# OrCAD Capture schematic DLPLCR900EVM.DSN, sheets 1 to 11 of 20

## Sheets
1 P20-Notes and Revisions
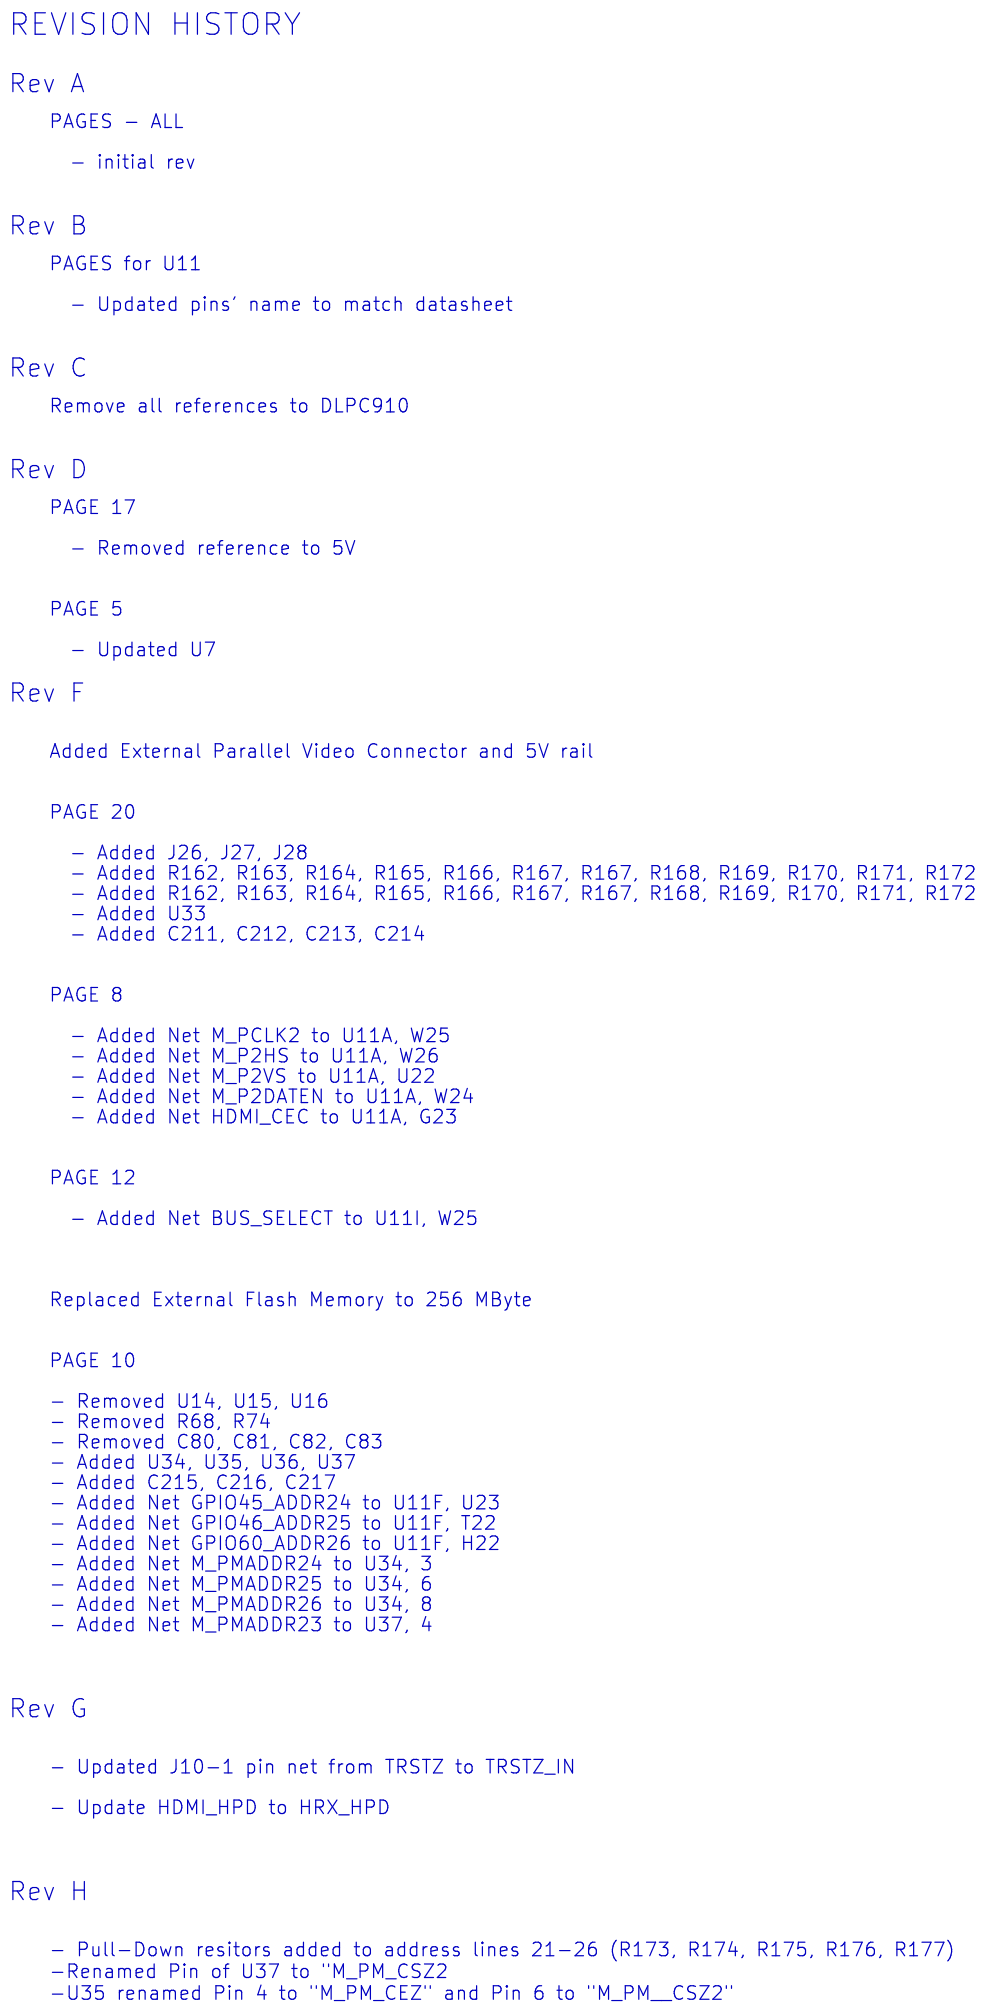
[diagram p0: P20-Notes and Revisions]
2 P19-External Parallel Source: size A3
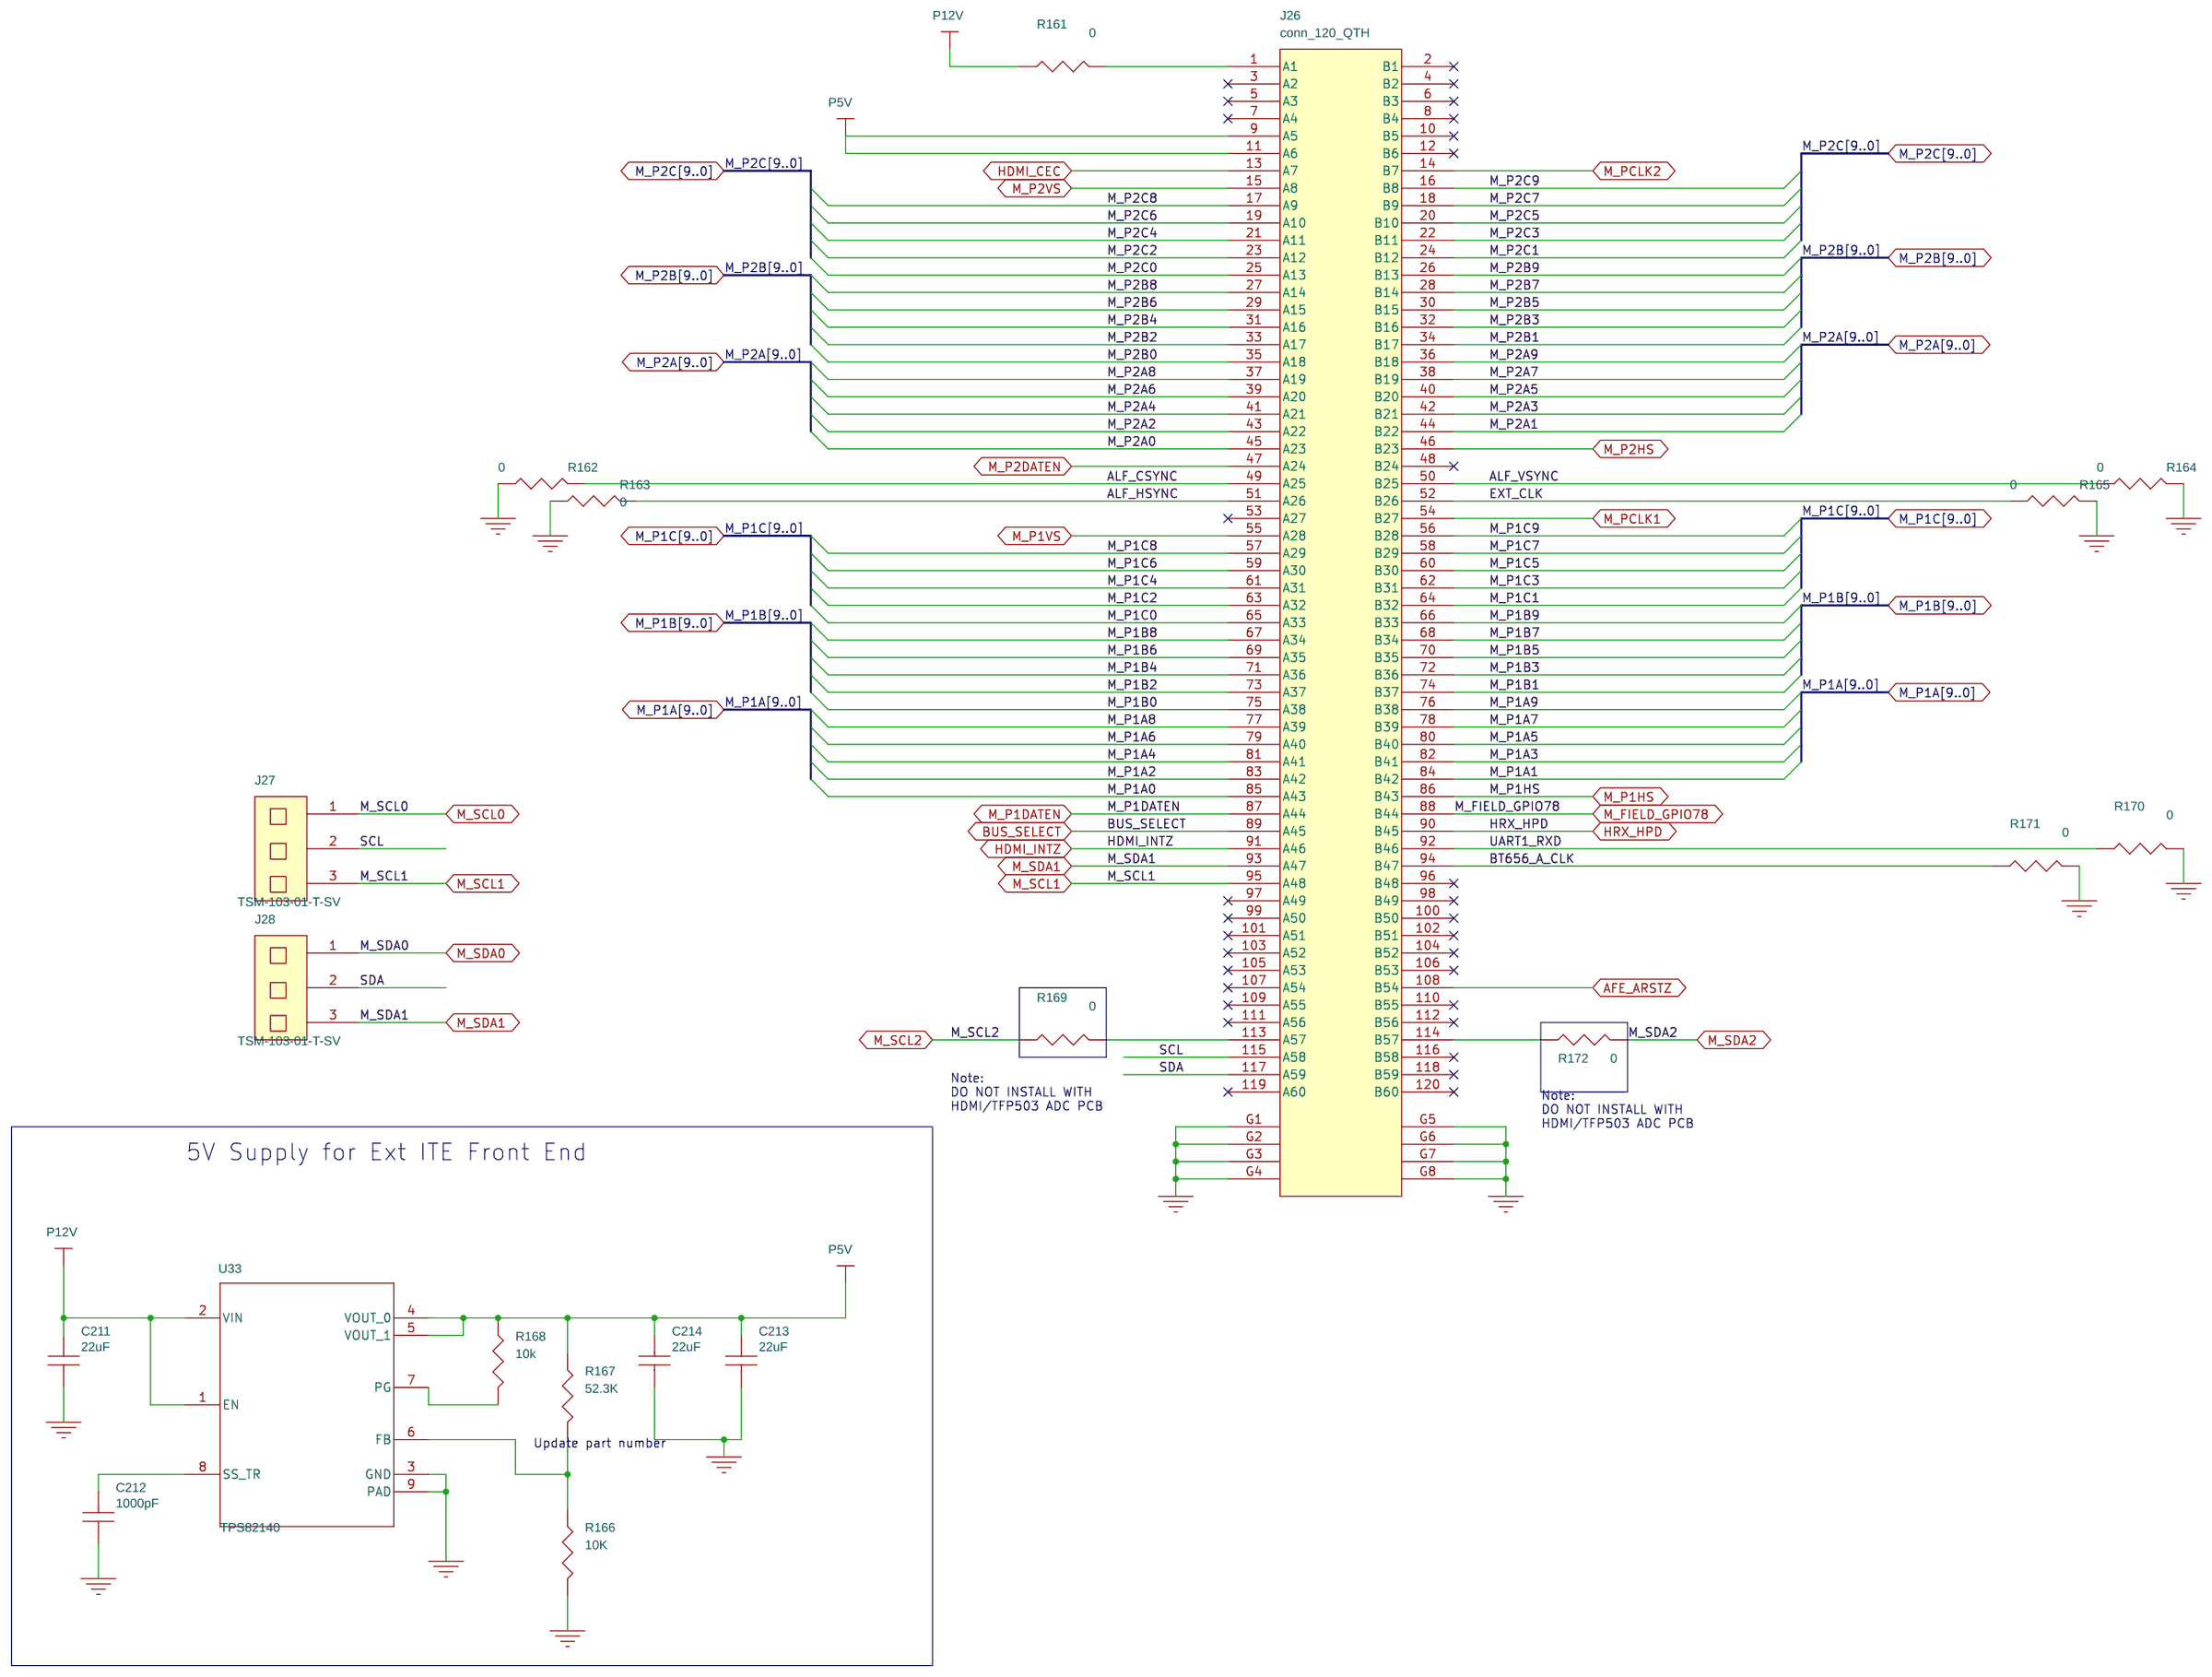
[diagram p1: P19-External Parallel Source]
3 P02-Import Notice
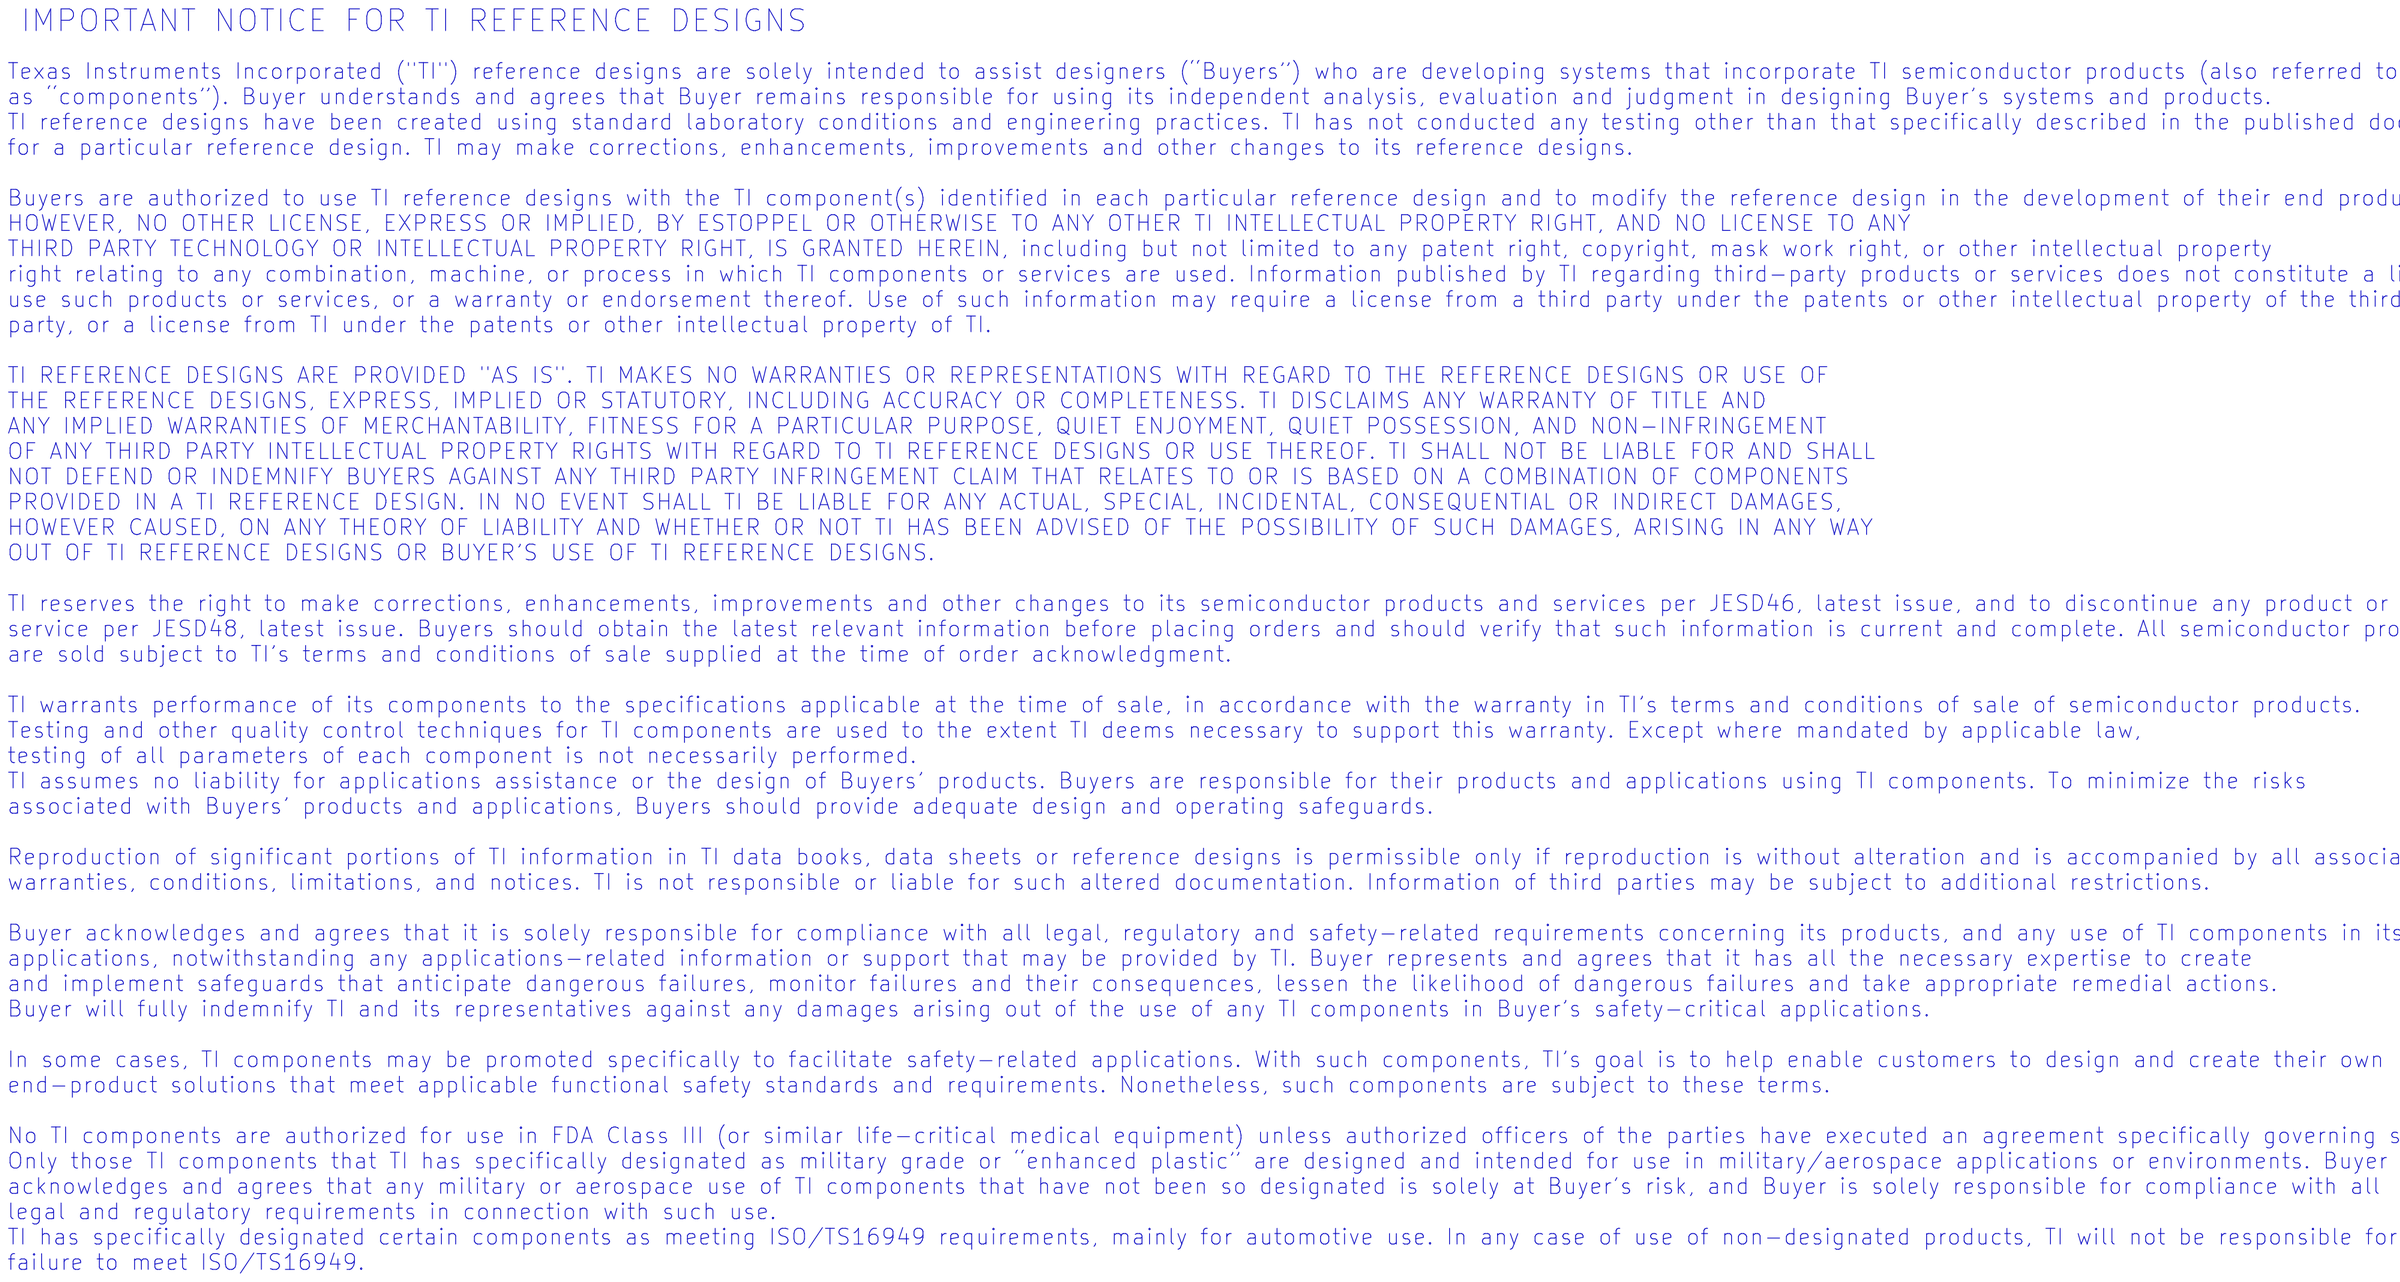
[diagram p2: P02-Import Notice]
4 P16-Power LDOs: size A3
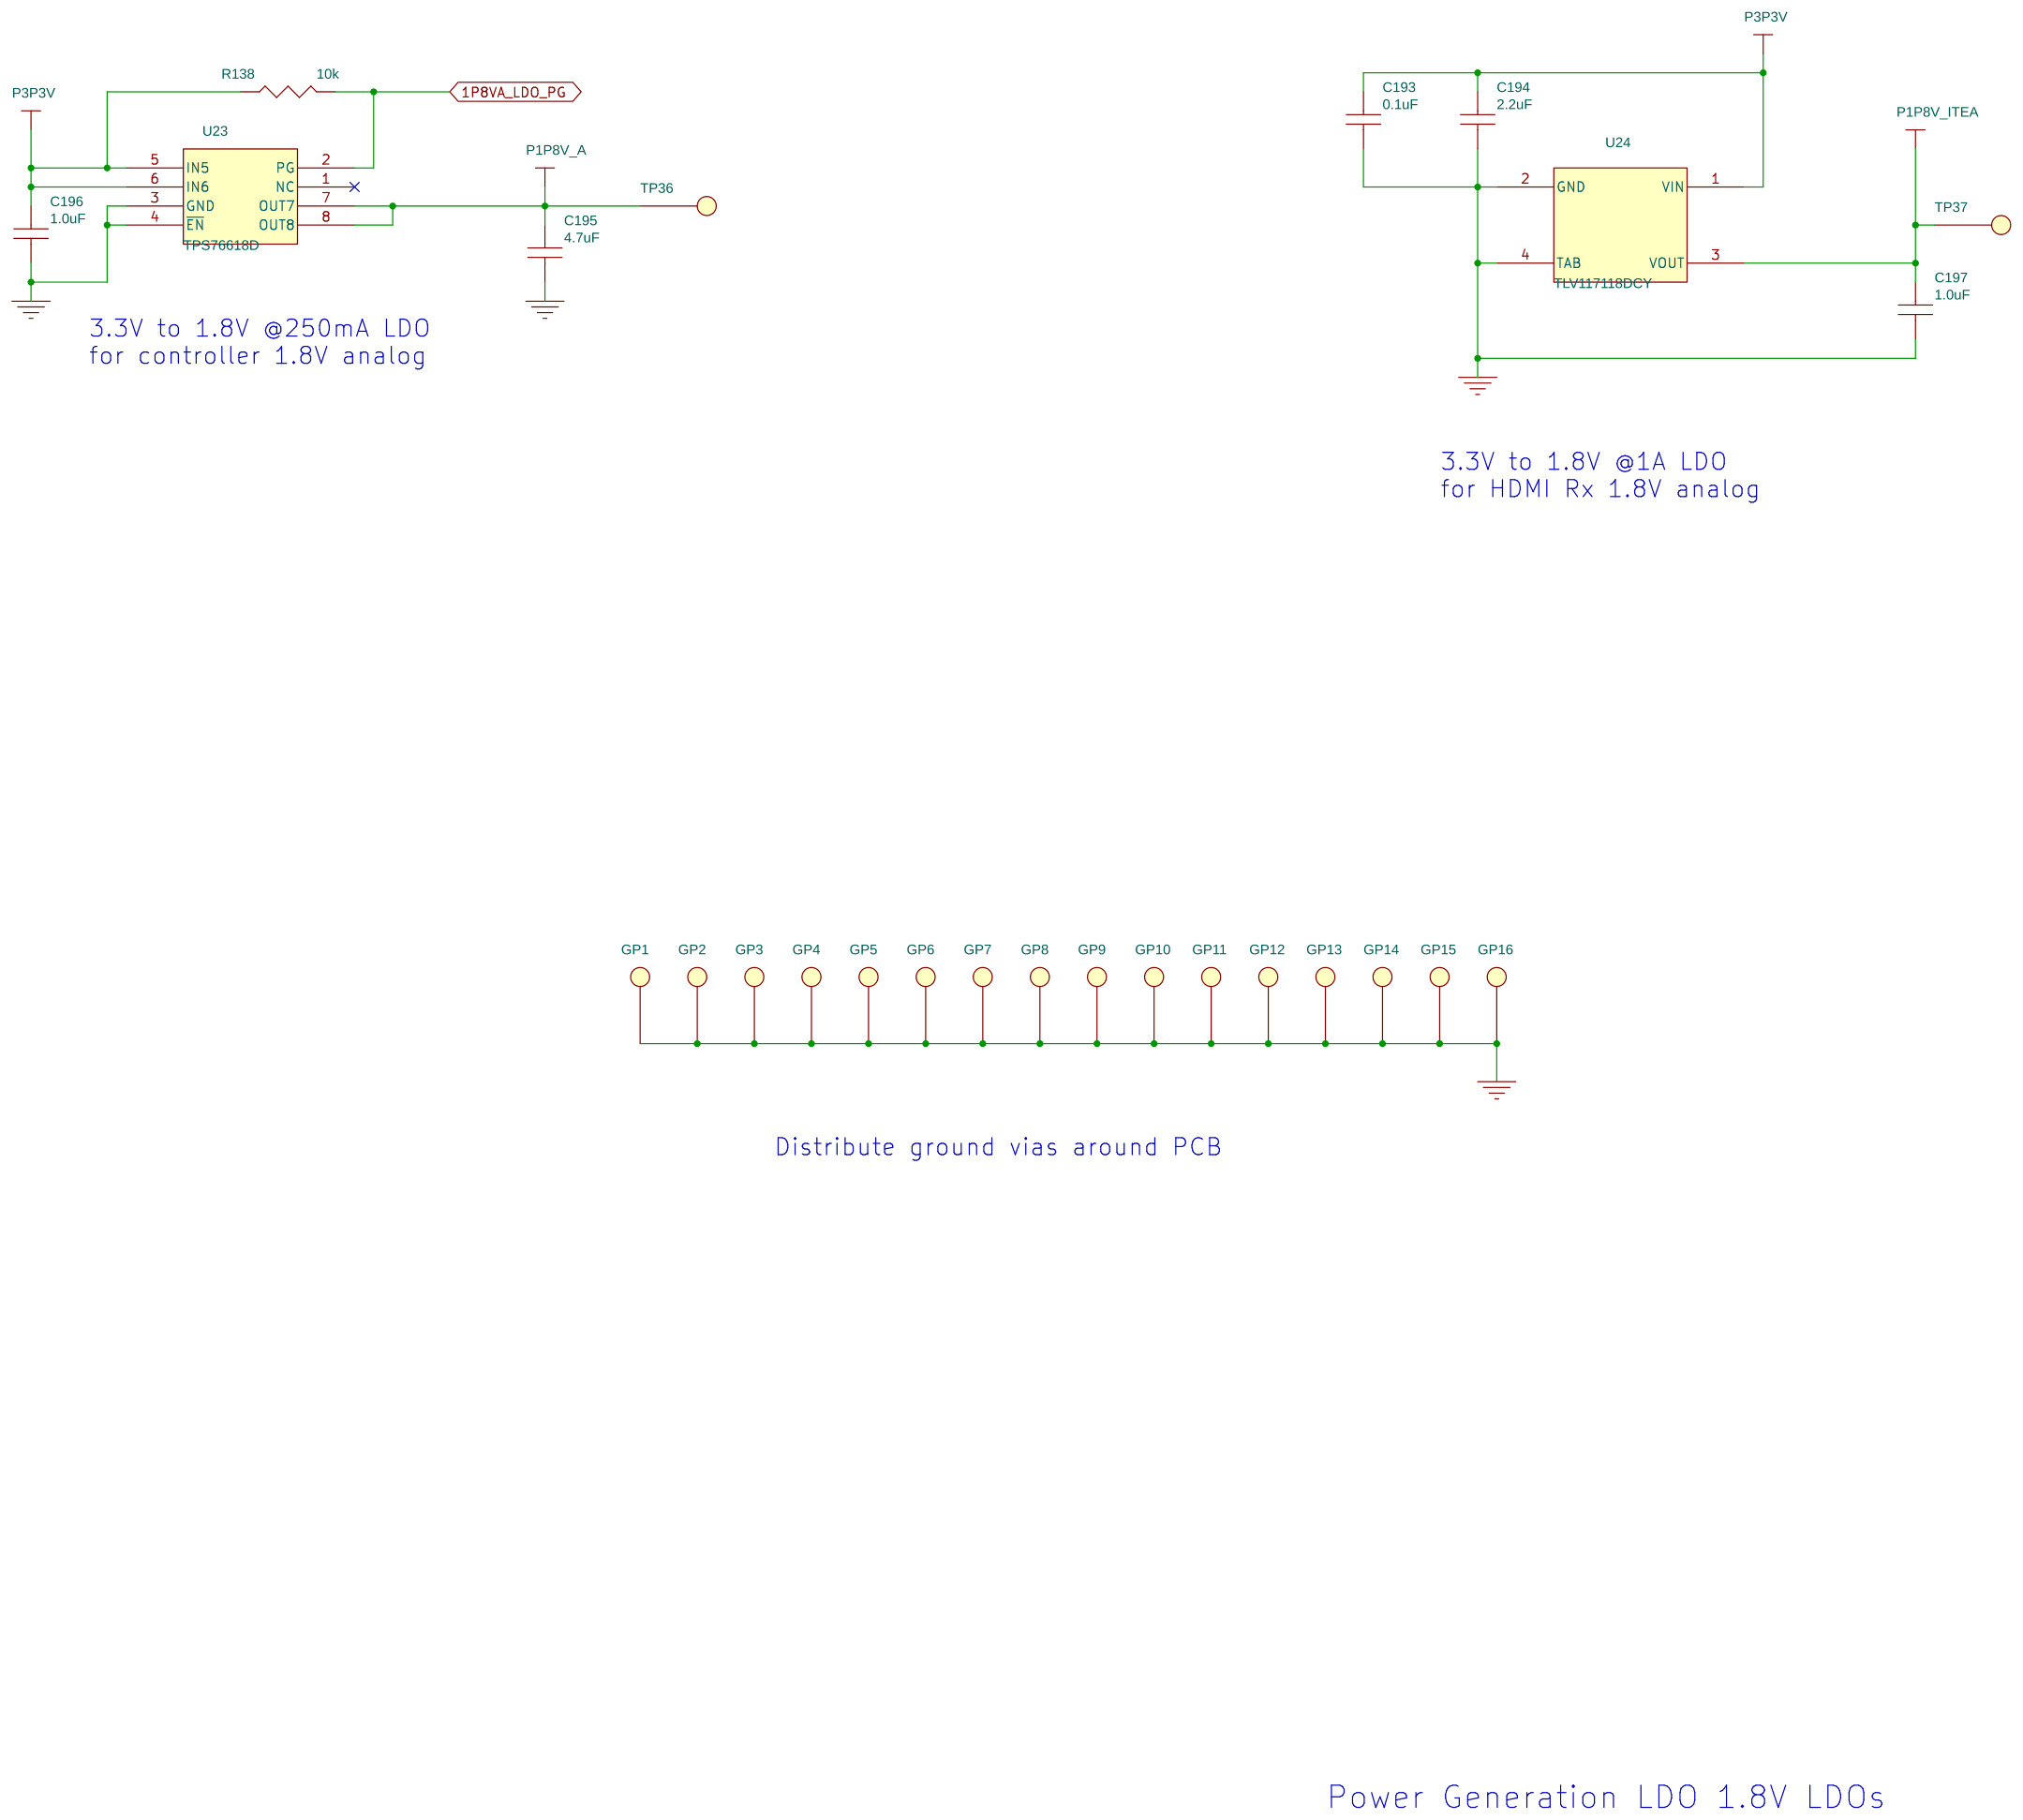
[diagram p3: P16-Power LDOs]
5 P15-Power 1.15V, 1.8V, 3.3V: size A3
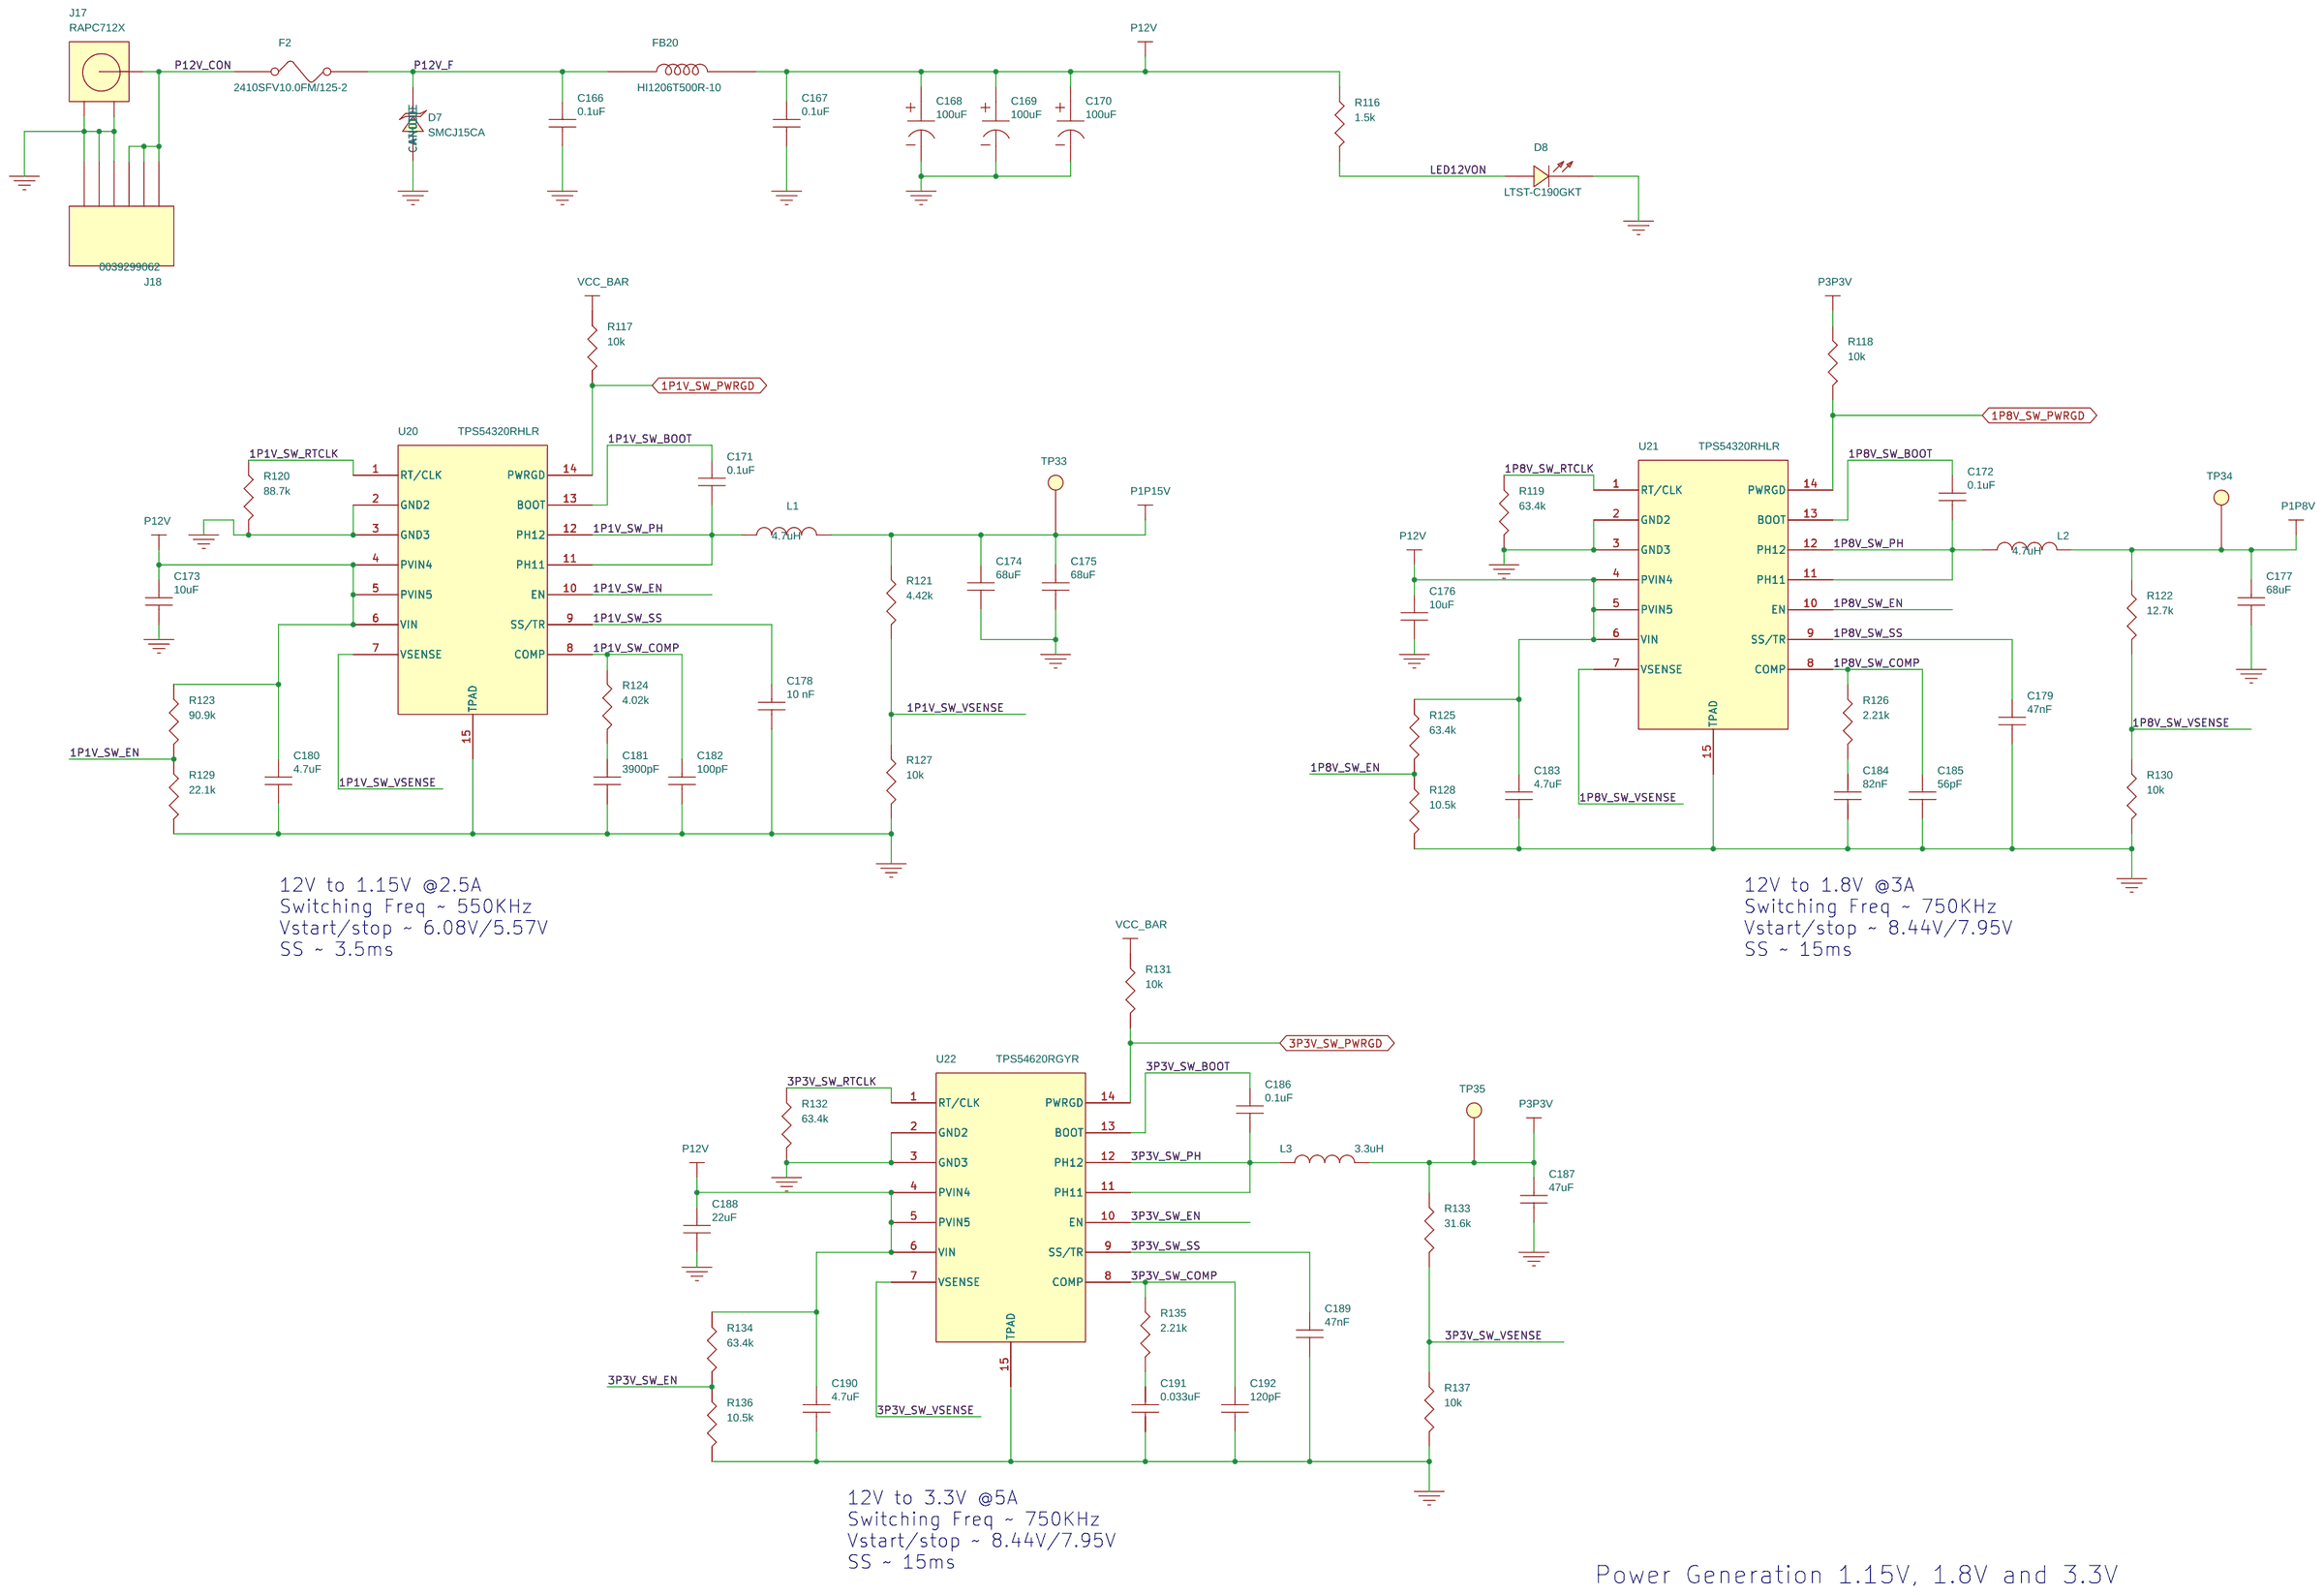
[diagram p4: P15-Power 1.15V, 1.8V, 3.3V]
6 P14-DMD Flex Connector: size A3
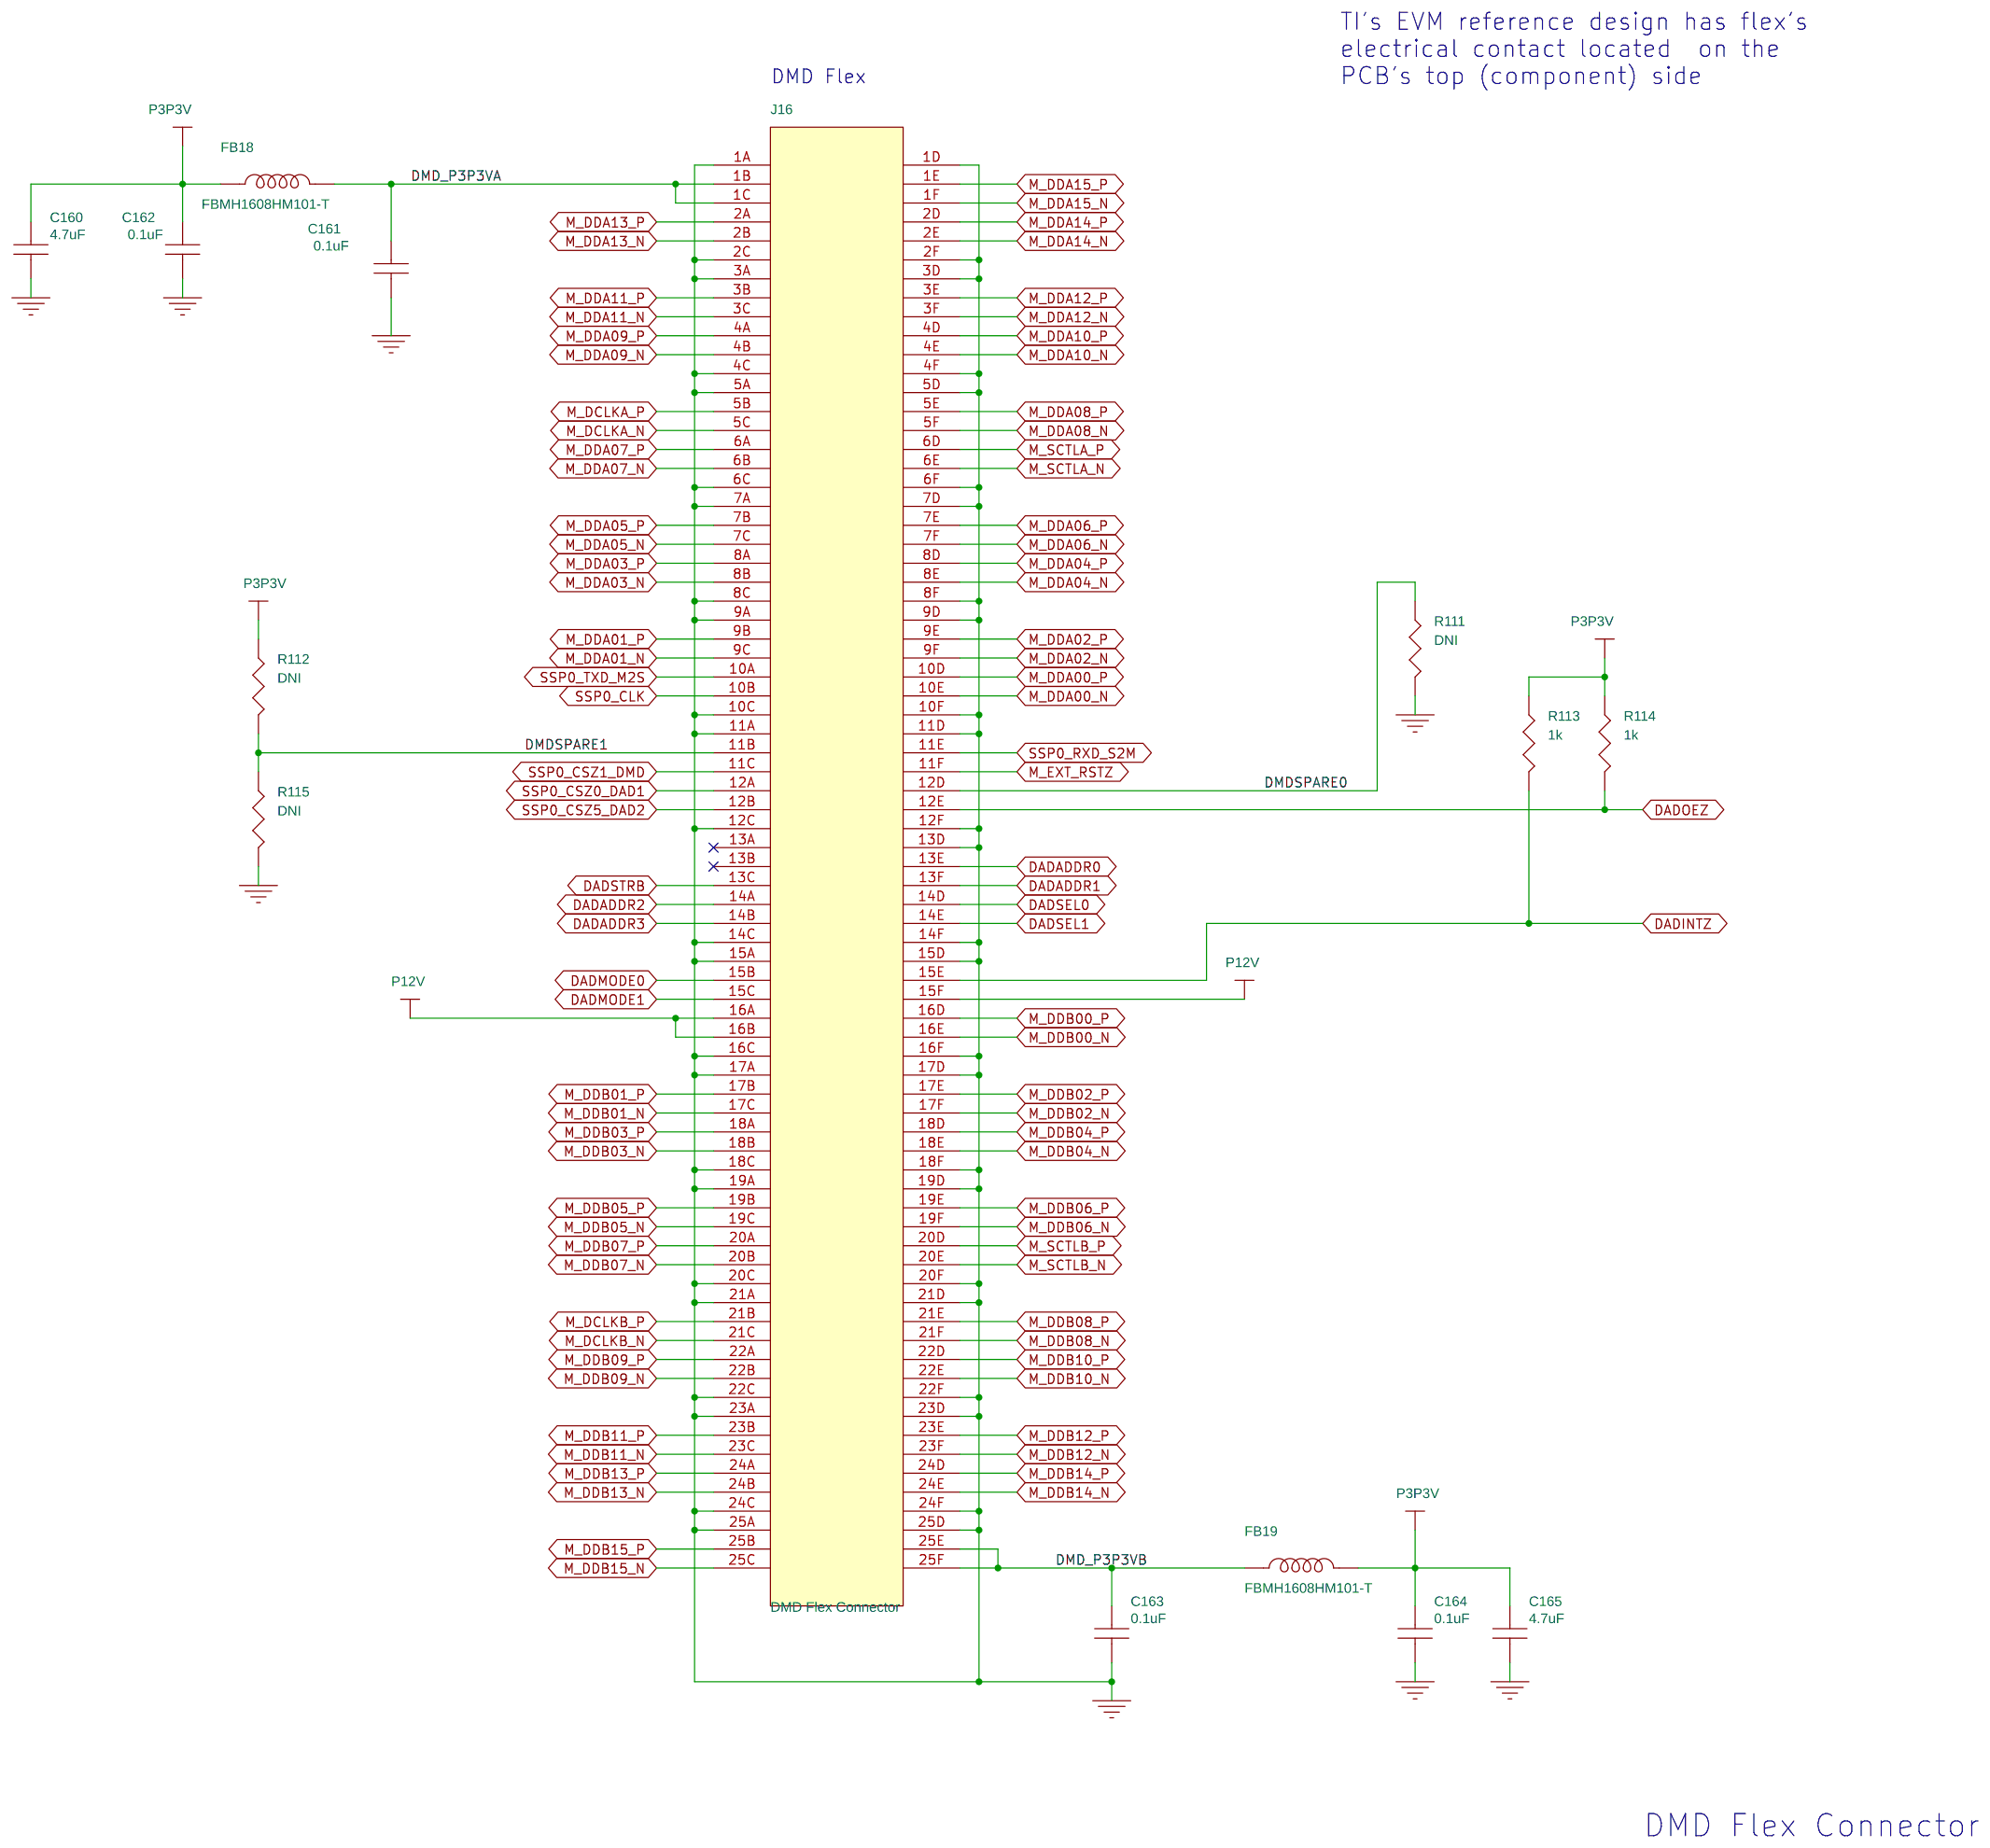
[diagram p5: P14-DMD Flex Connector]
7 P17-Inout Trigger, LED Driver: size A3
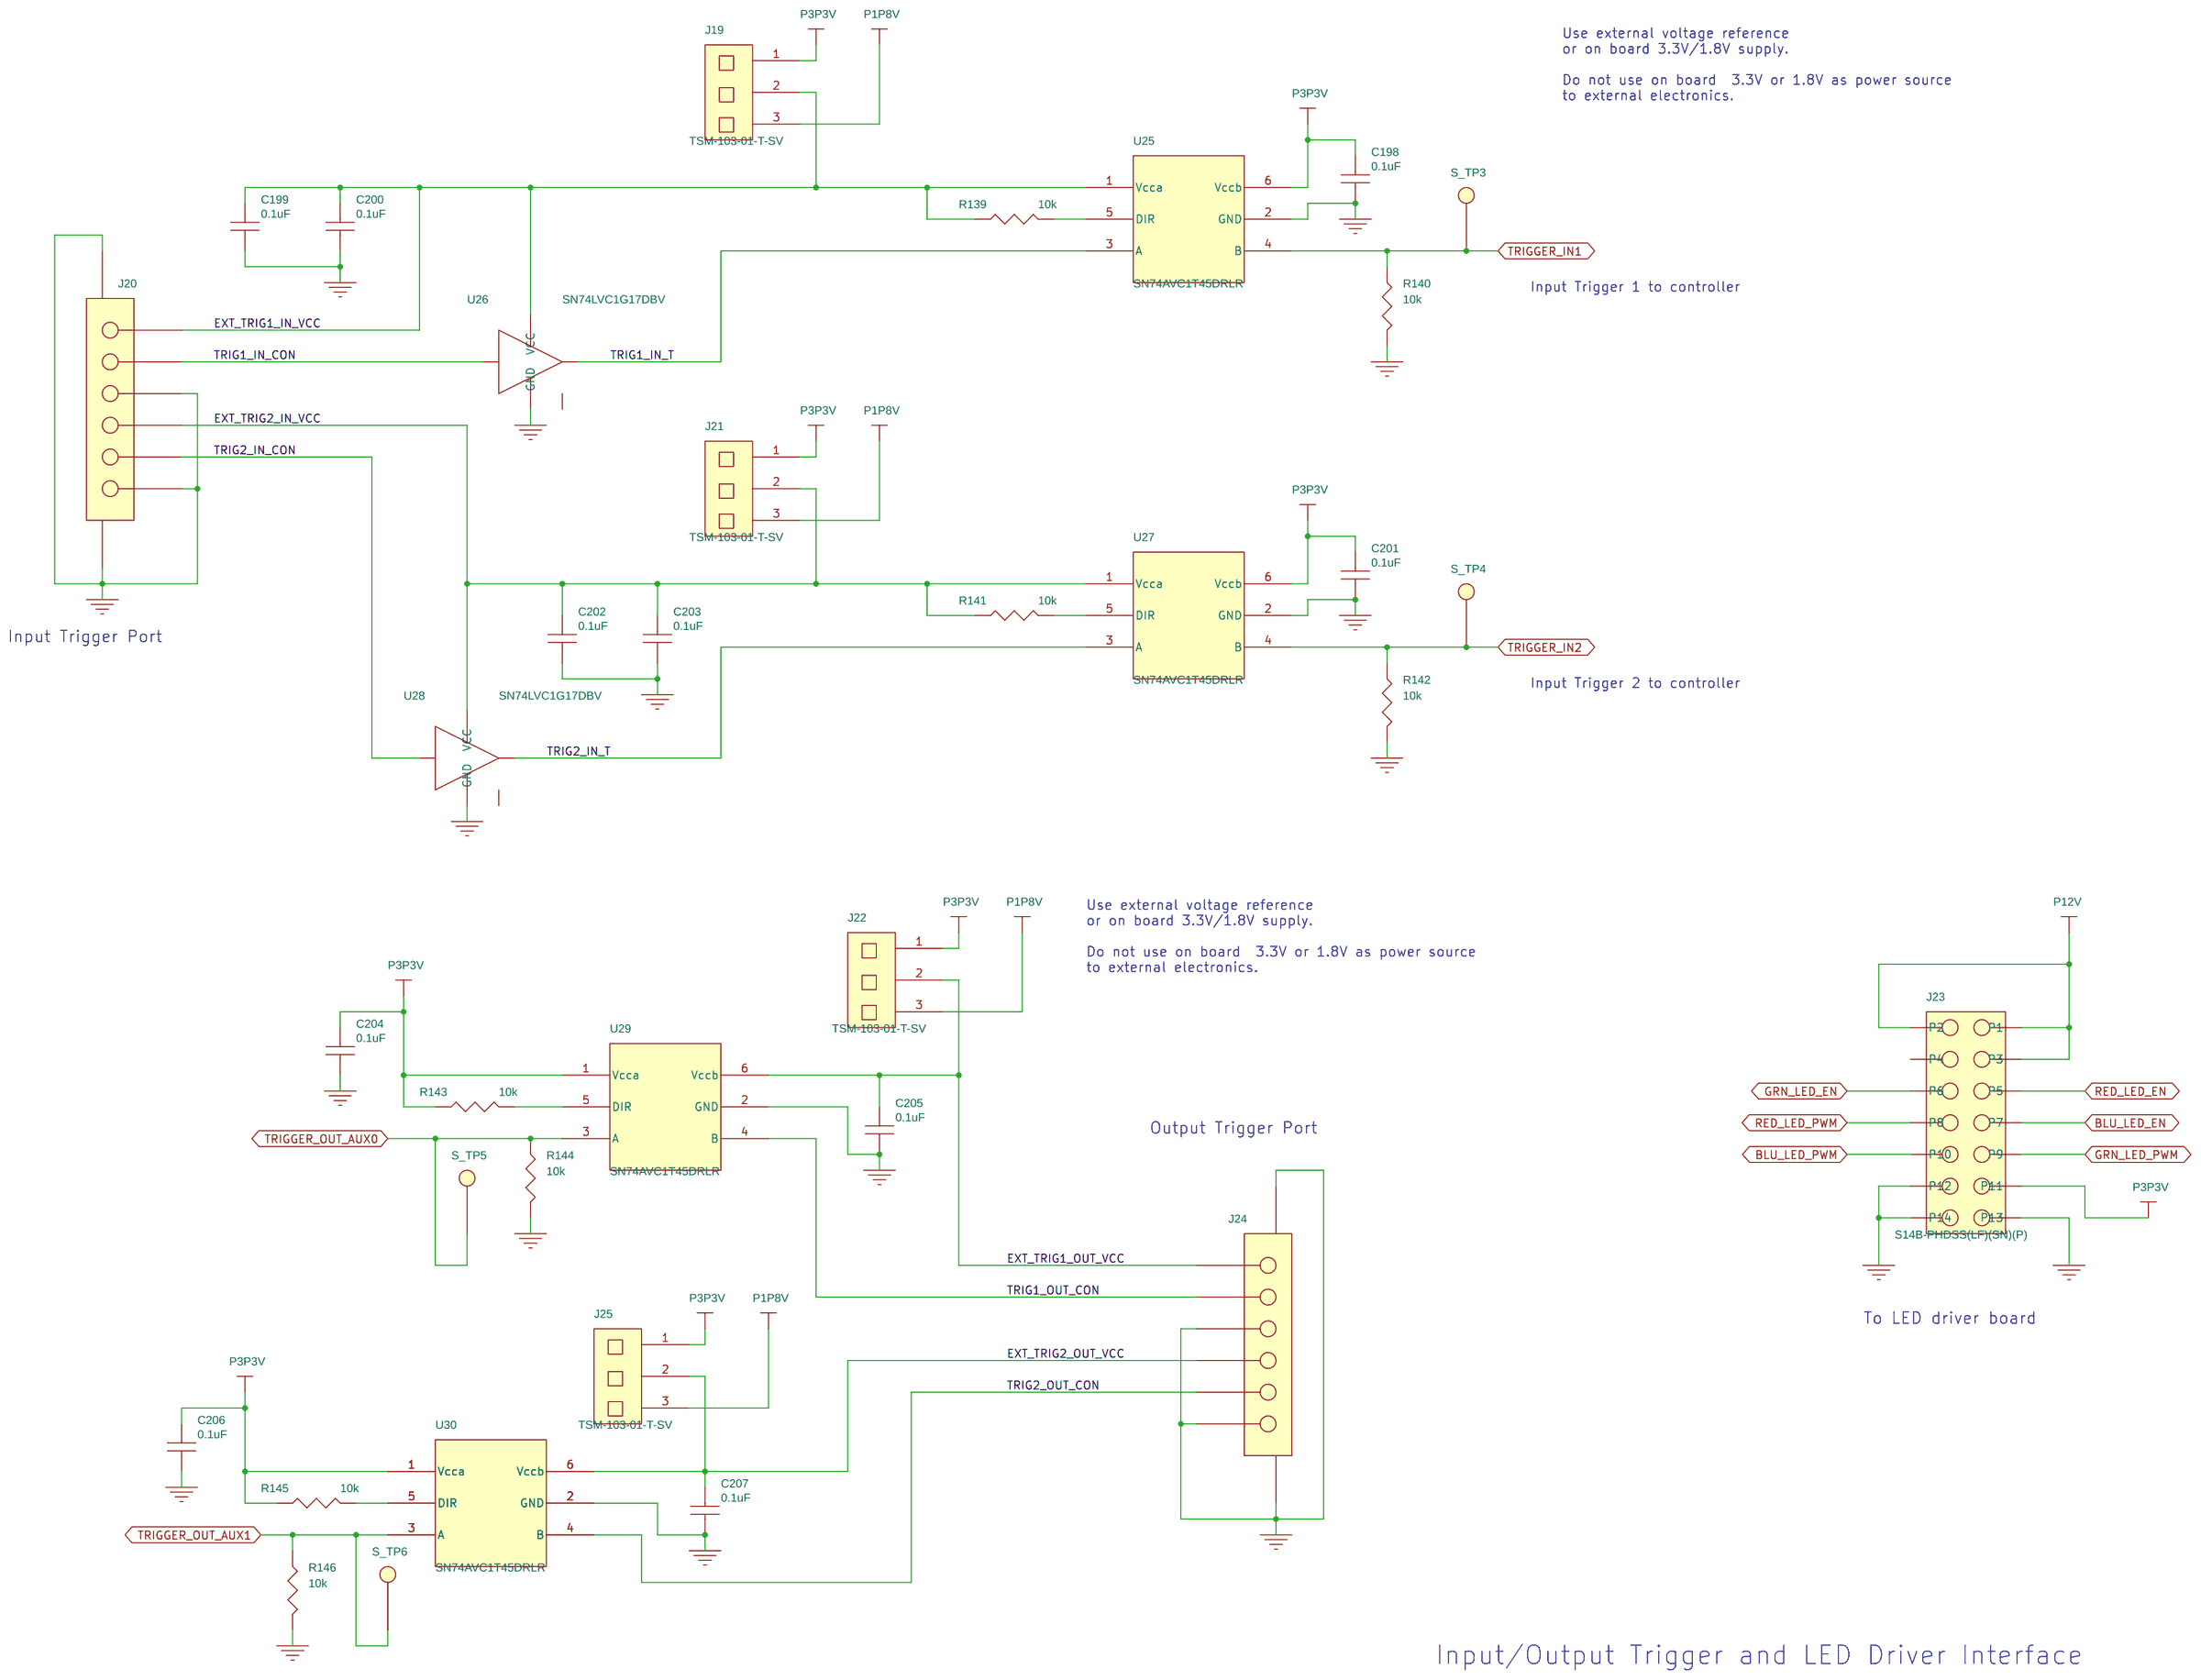
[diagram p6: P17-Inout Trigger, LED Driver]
8 P18-Gen pwrgood posense clk: size A3
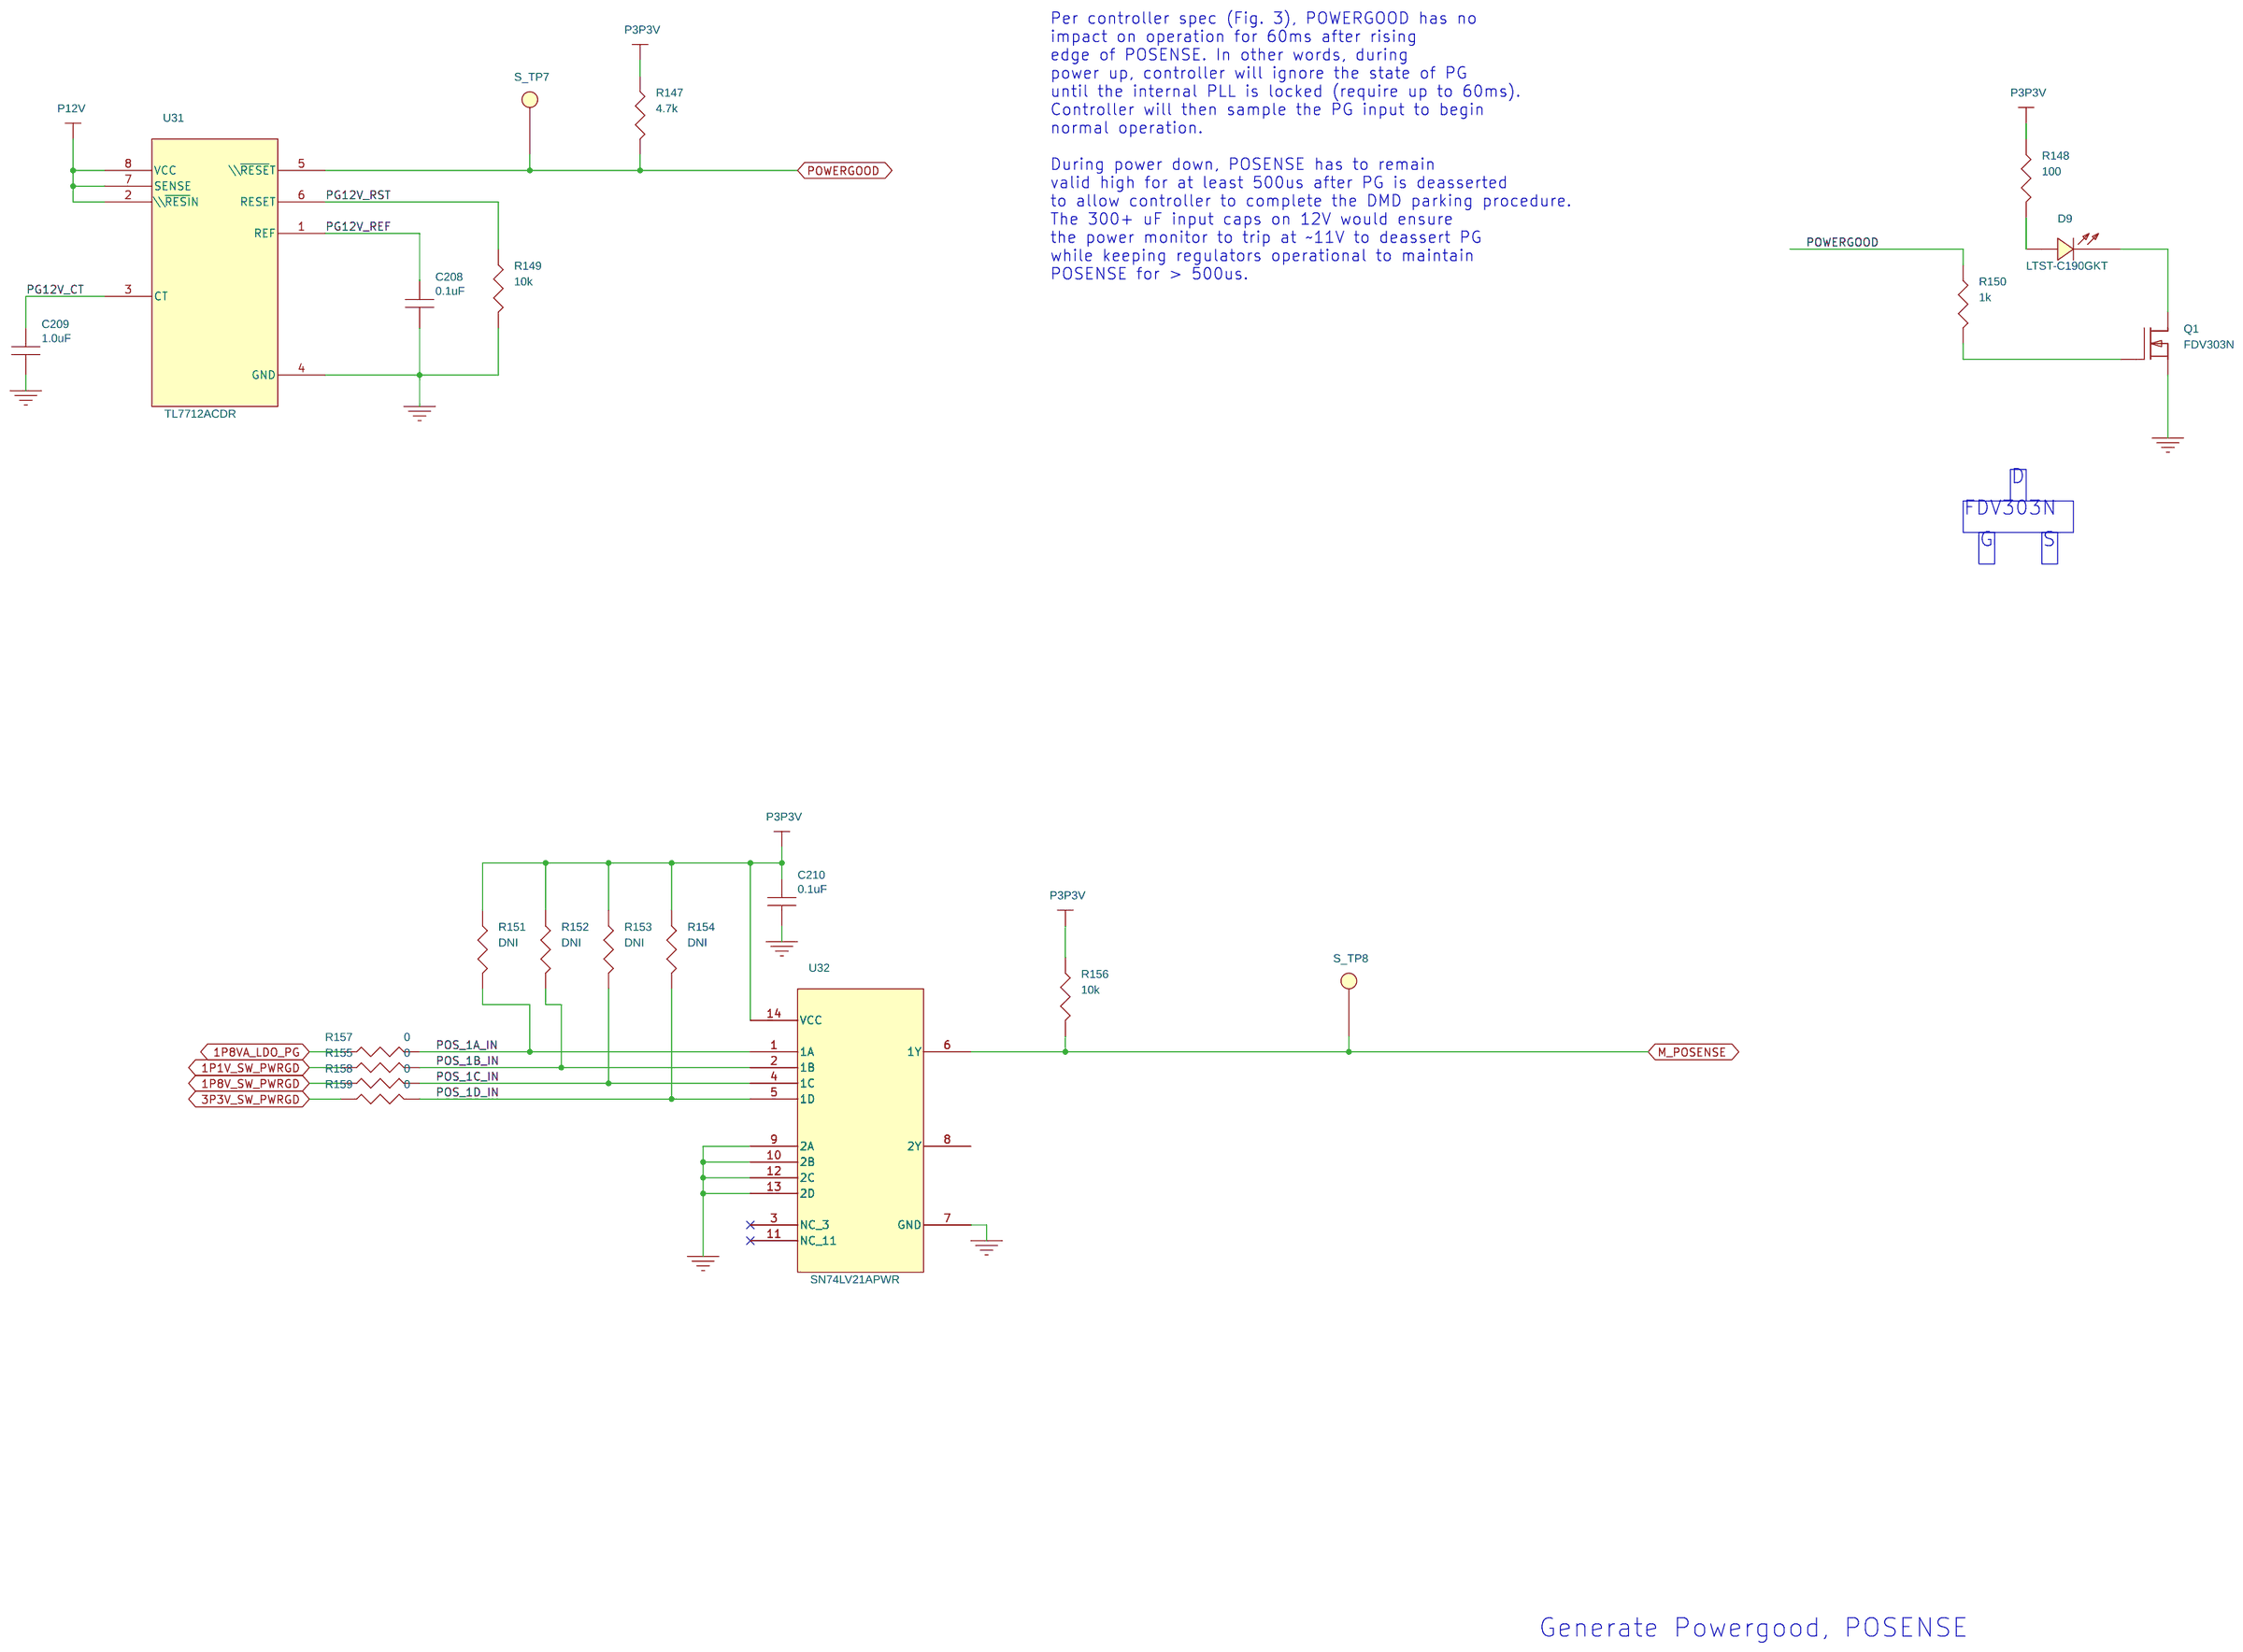
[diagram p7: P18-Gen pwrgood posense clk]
9 P12-Controller I2C Trig GPIO: size A3
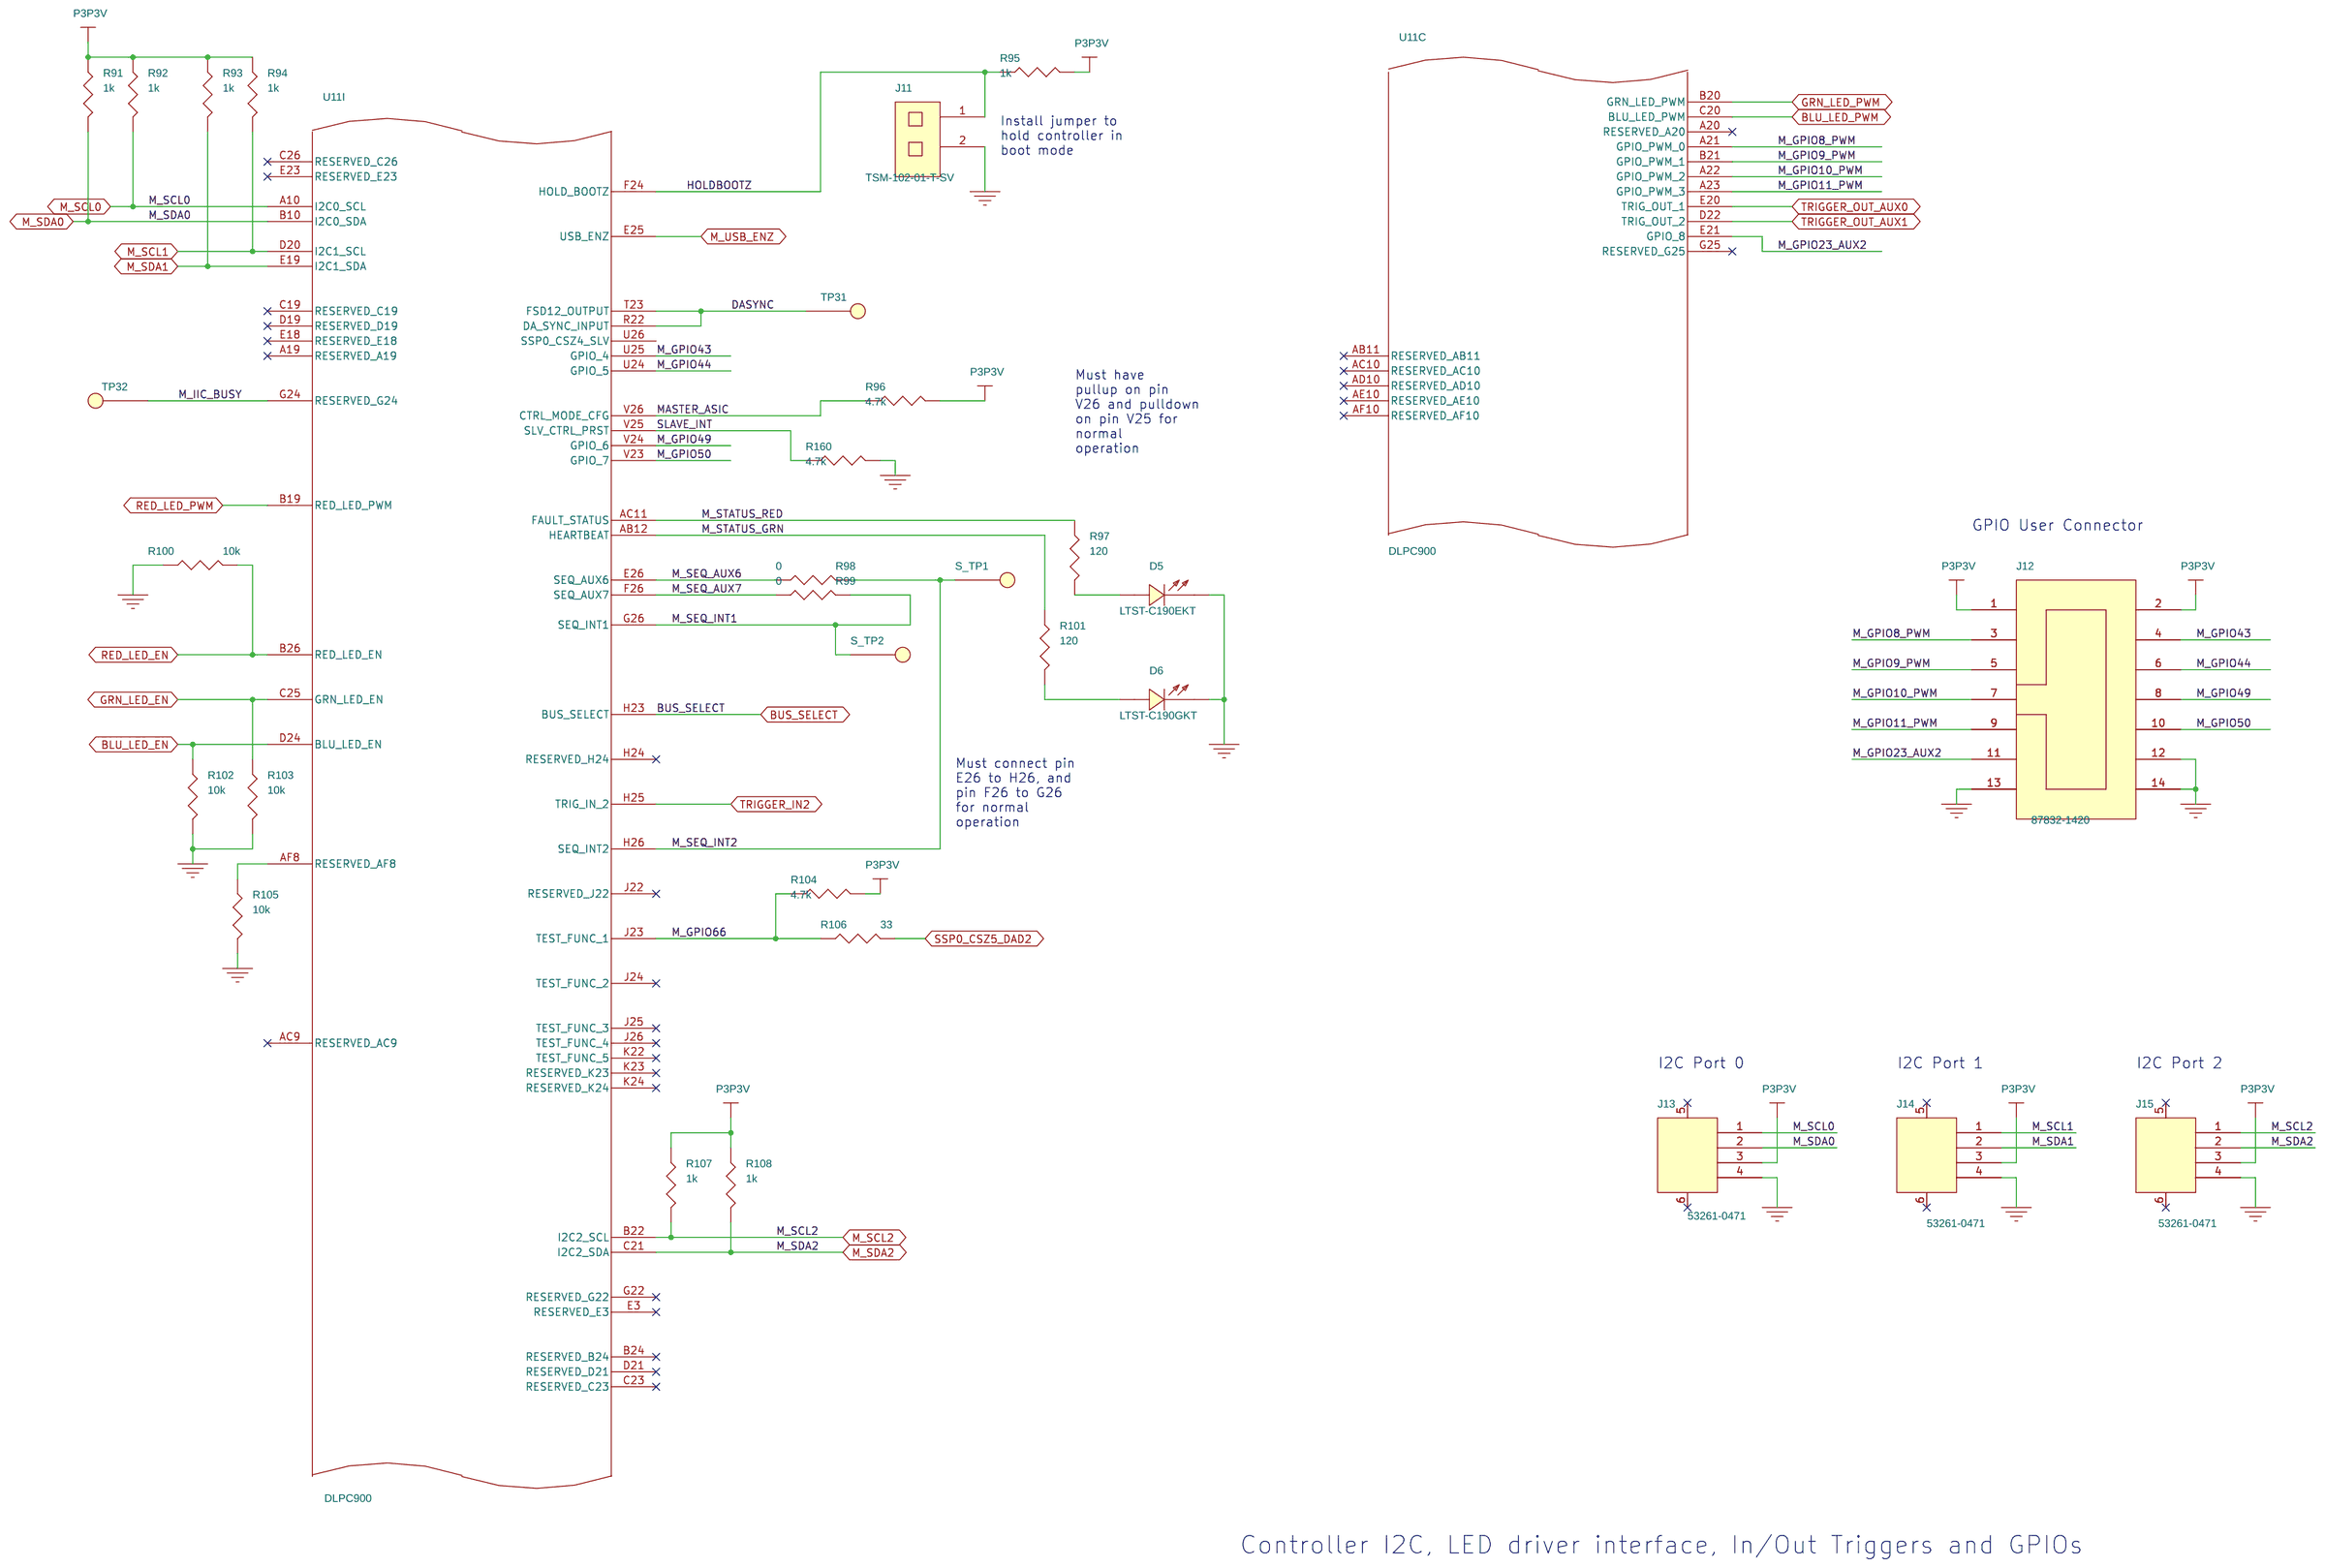
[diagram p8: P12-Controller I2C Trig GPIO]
10 P11-Controller ICE JTAG: size A3
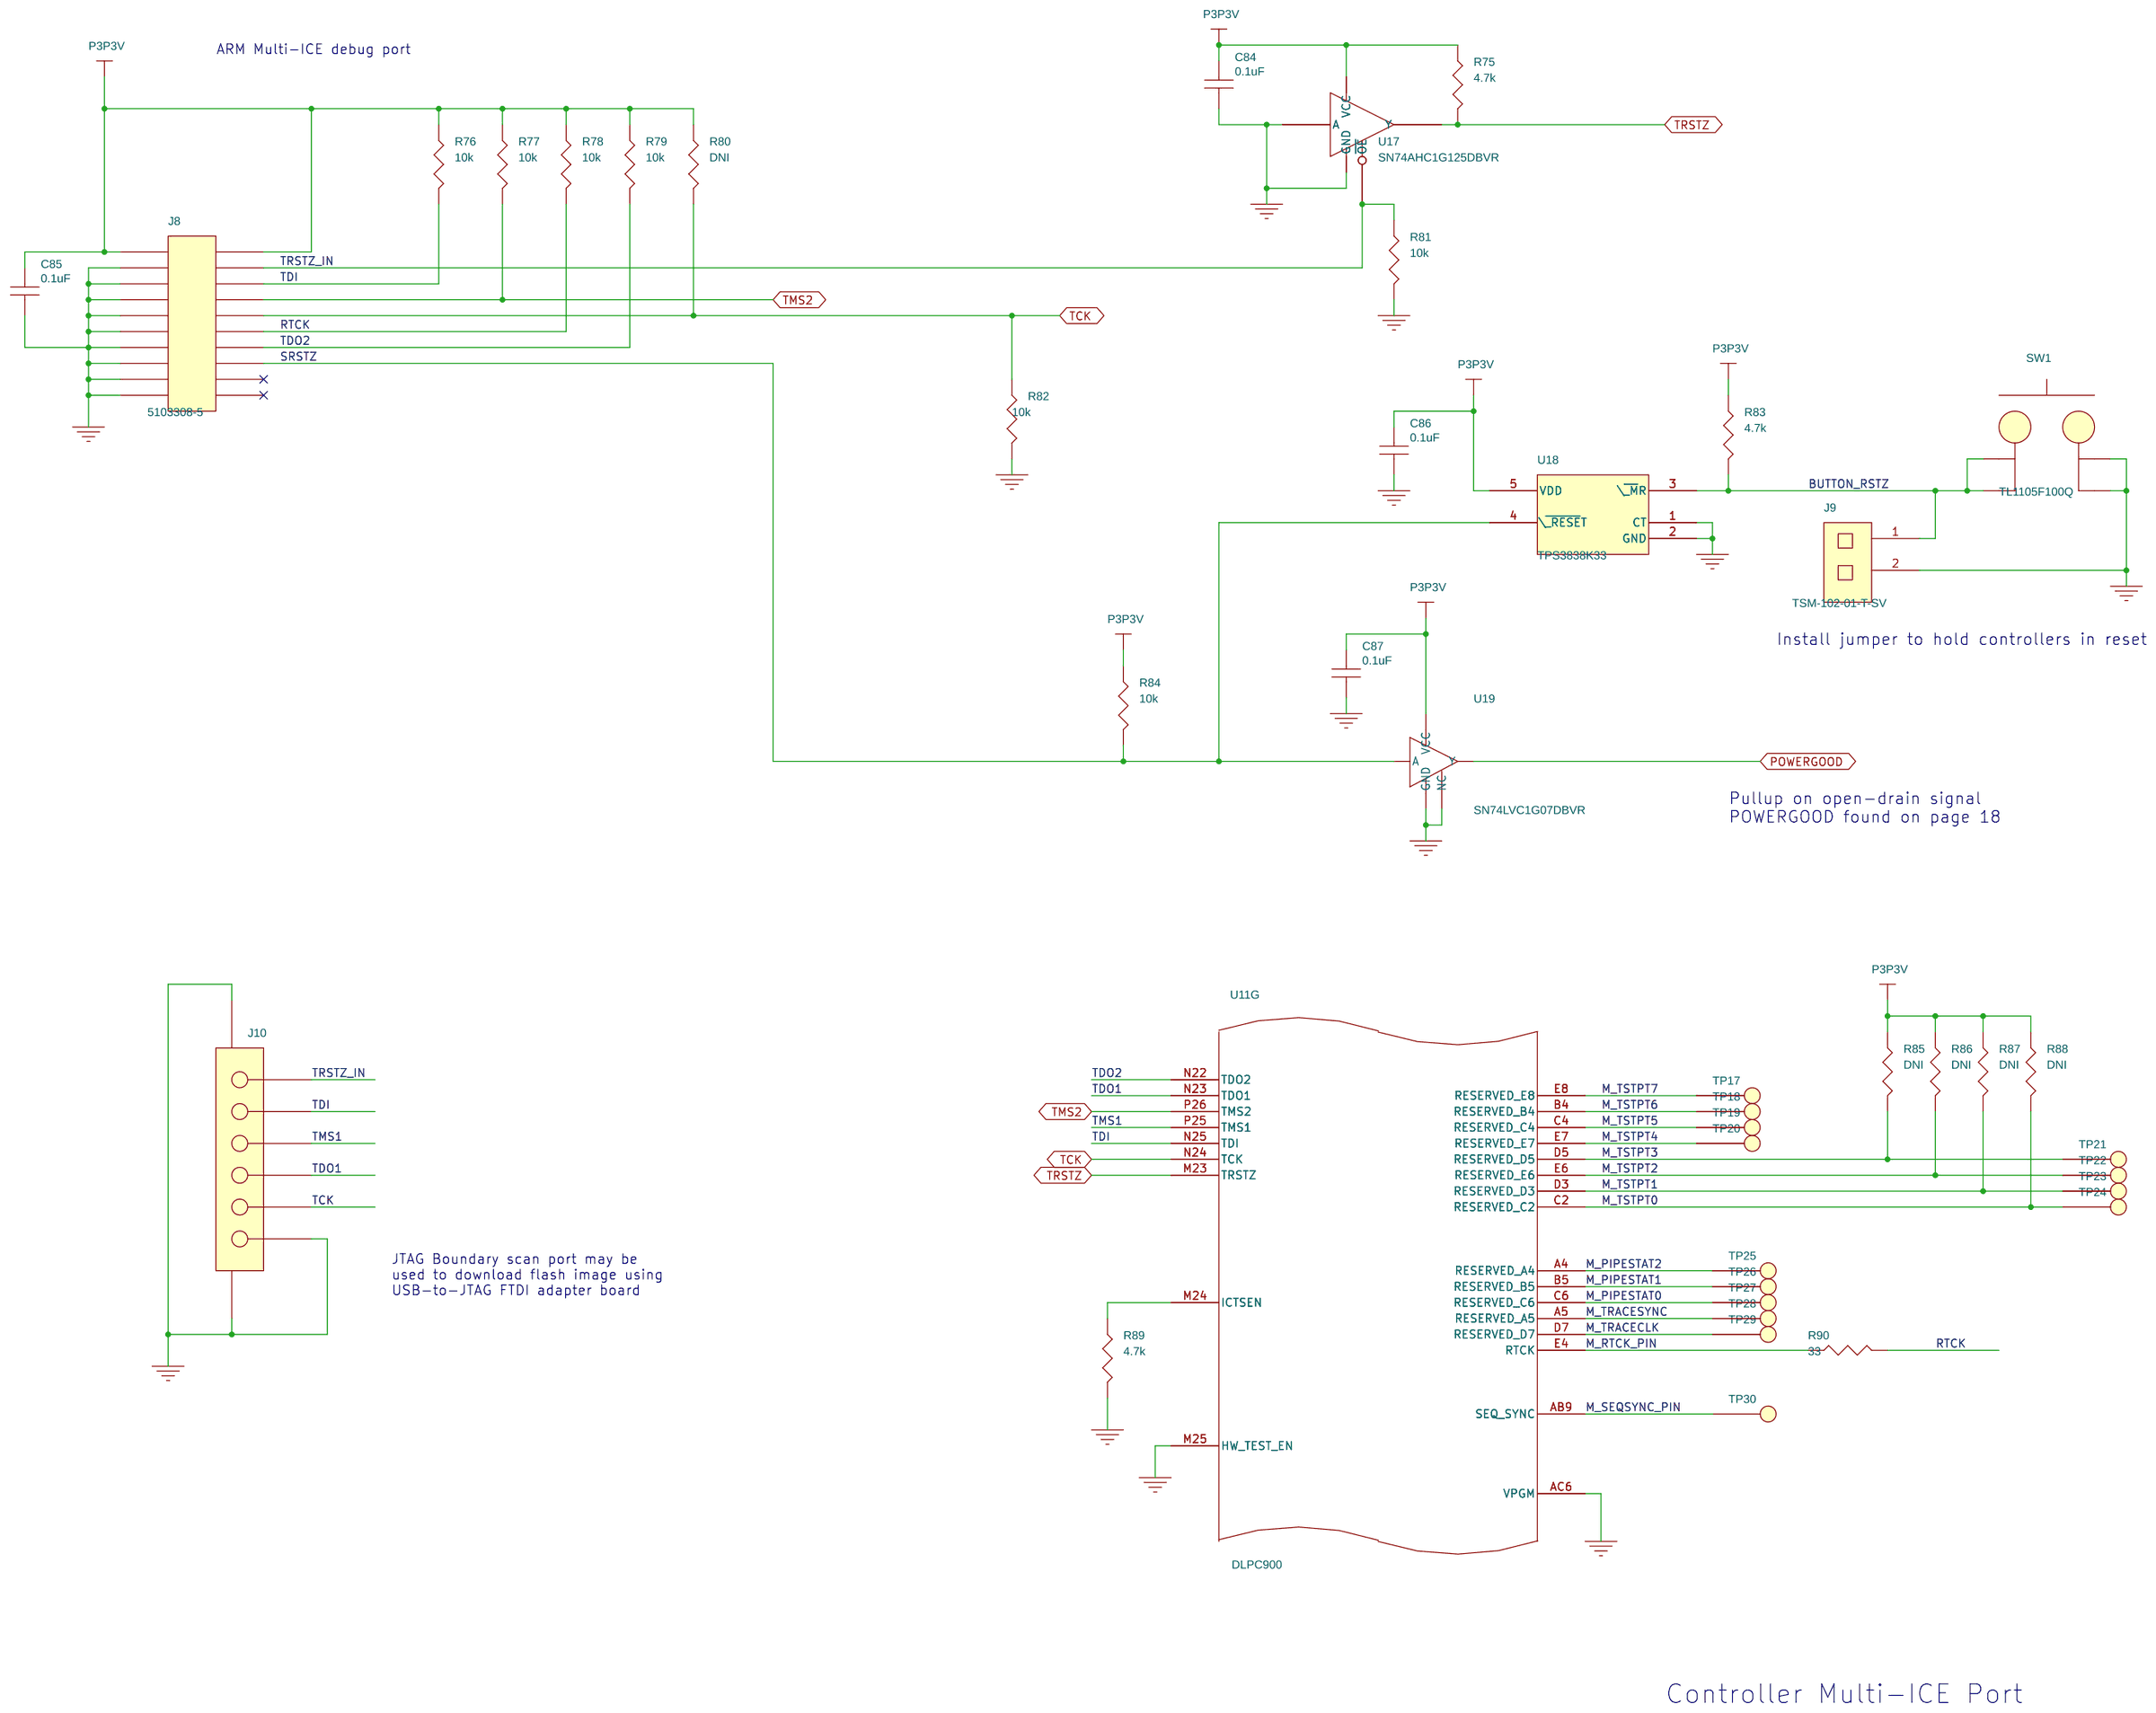
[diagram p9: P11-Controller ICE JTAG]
11 P10-Controller Ext Flash Intf: size A3
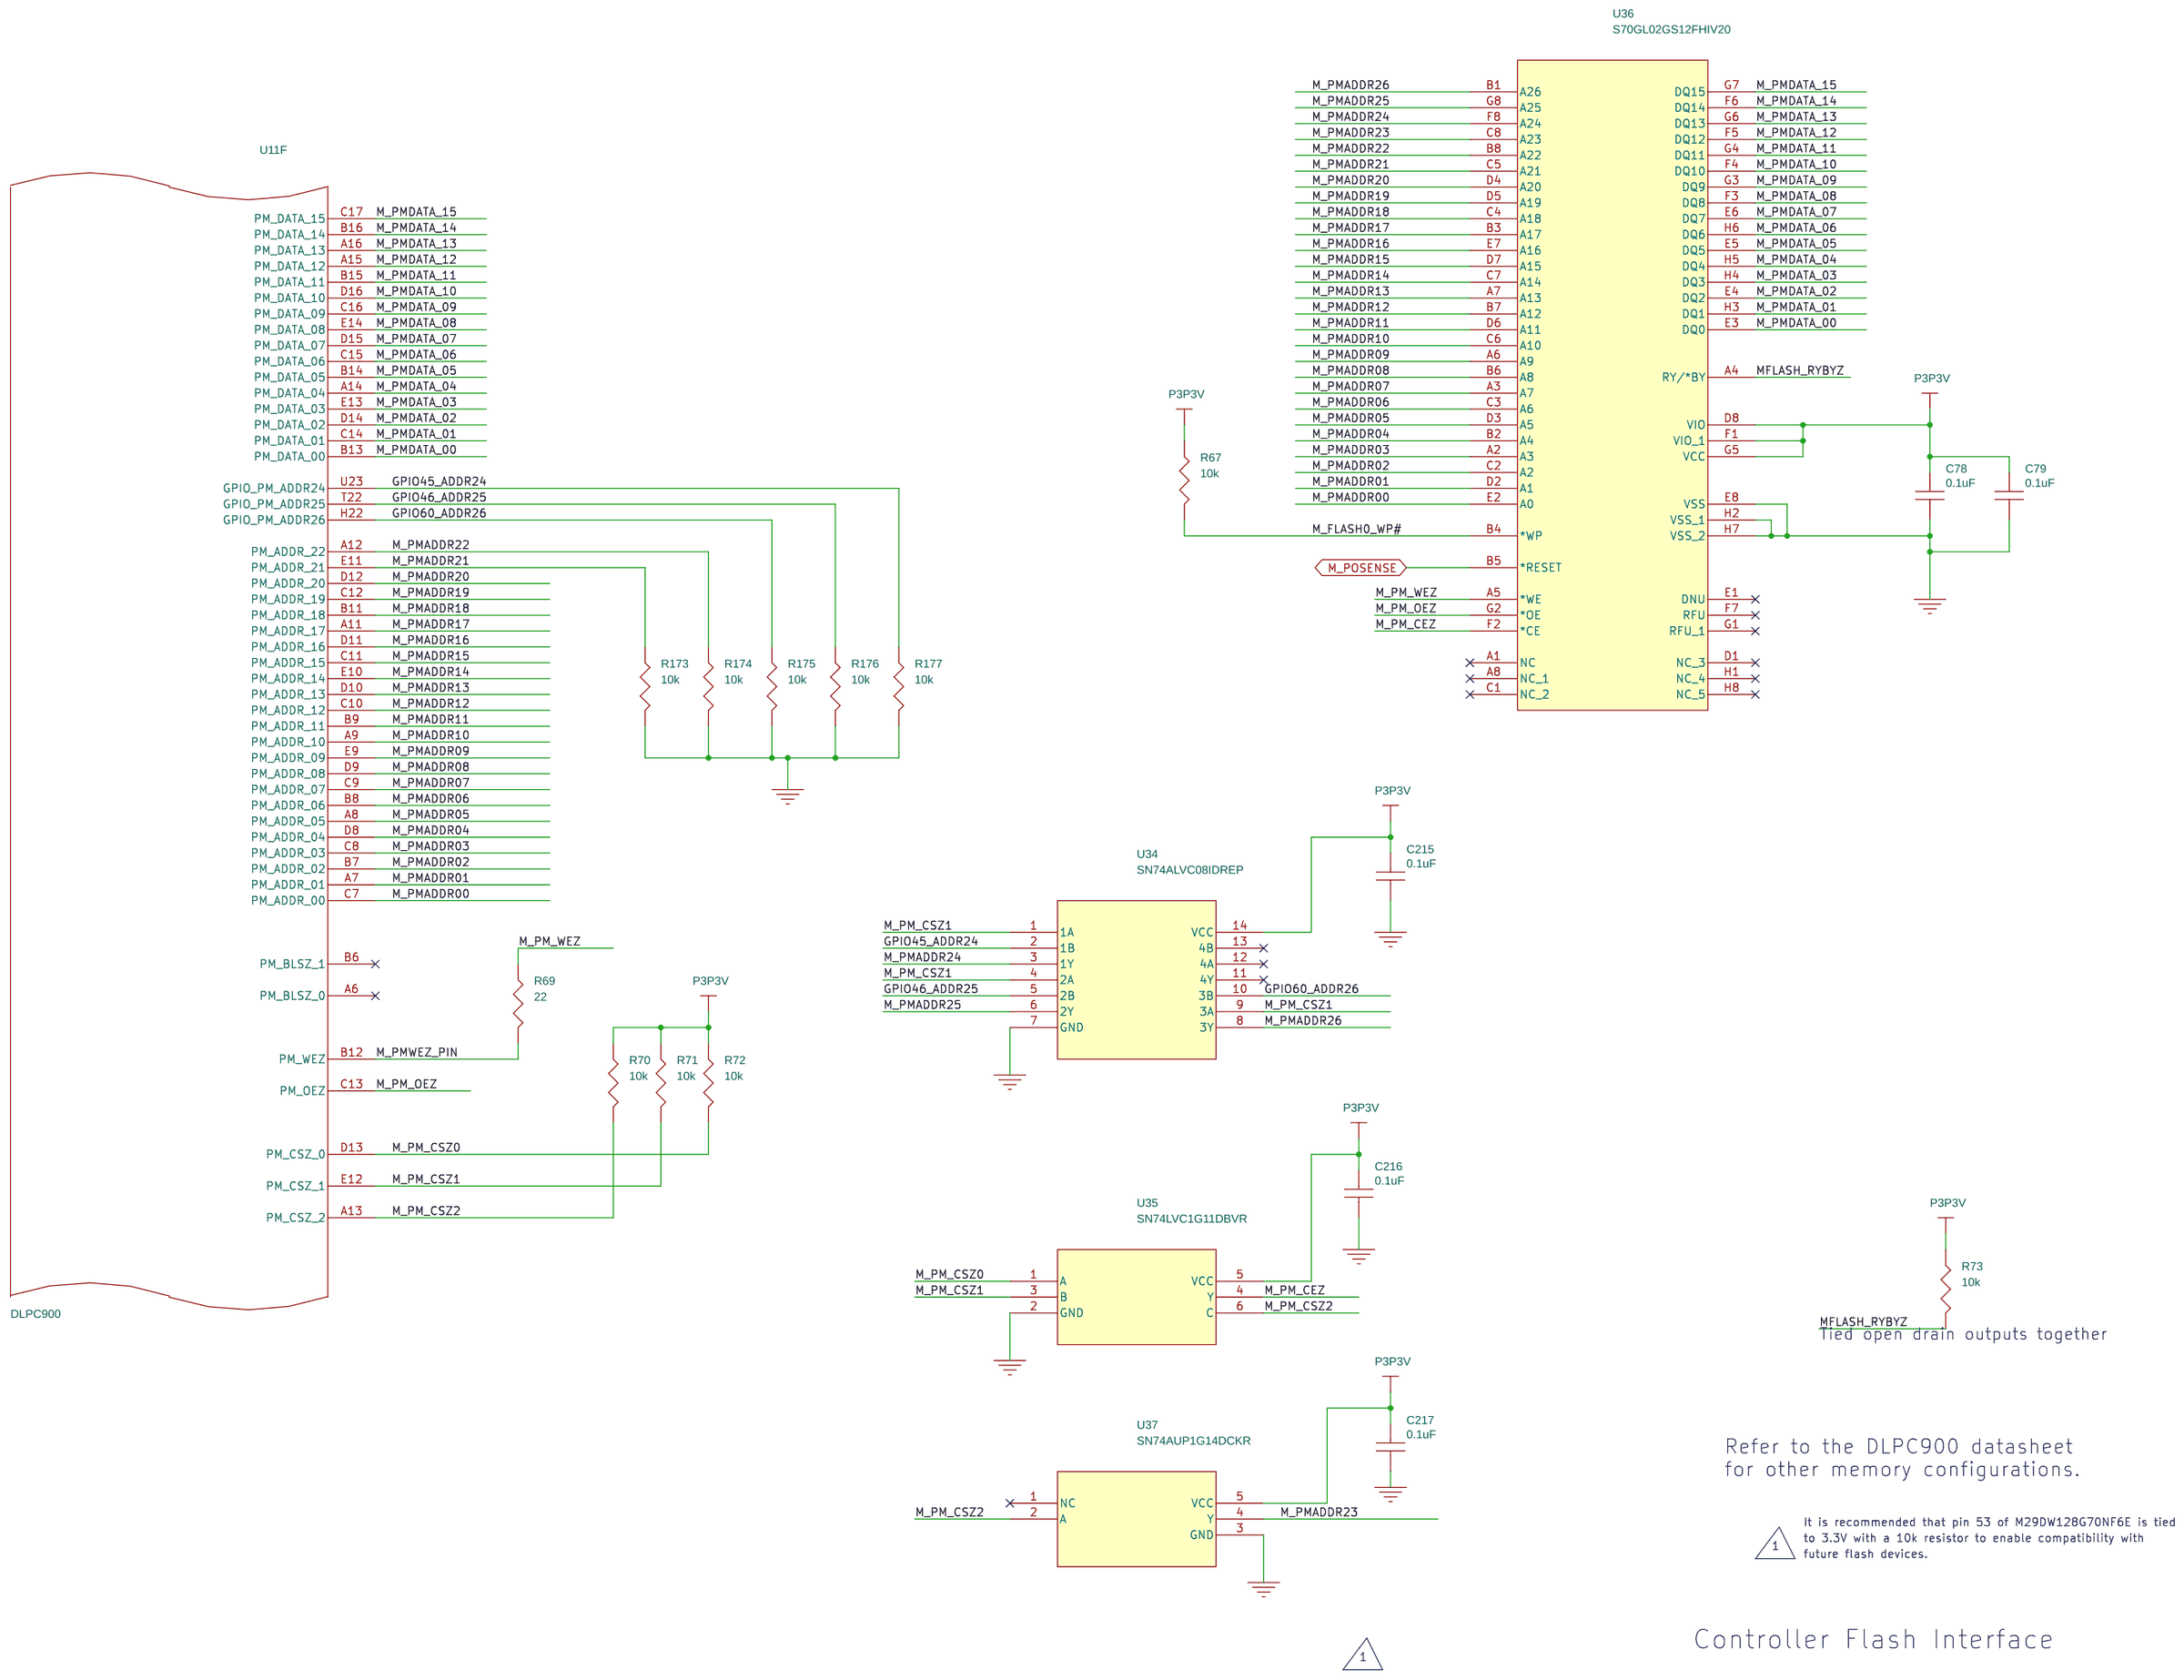
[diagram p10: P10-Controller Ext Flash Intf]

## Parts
sheet P10-Controller Ext Flash Intf
C78  0.1uF  [0402]
C79  0.1uF  [0402]
C215  0.1uF  [0402]
C216  0.1uF  [0402]
C217  0.1uF  [0402]
R67  10k  [0402]
R69  22  [0402]
R70  10k  [0402]
R71  10k  [0402]
R72  10k  [0402]
R73  10k  [0402]
R173  10k  [0402]
R174  10k  [0402]
R175  10k  [0402]
R176  10k  [0402]
R177  10k  [0402]
U11  DLPC900  [BGA516-DDP_TI]  (sections A,B,C,D,E,F,G,H,I,J)
U34  SN74ALVC08IDREP  [SOIC127P600X175-14N]
U35  SN74LVC1G11DBVR  [SOT23_6]
U36  S70GL02GS12FHIV20  [BGA64C100P8X8_1100X1300X140]
U37  SN74AUP1G14DCKR  [SC70_5p]
sheet P11-Controller ICE JTAG
C84  0.1uF  [0402]
C85  0.1uF  [0402]
C86  0.1uF  [0402]
C87  0.1uF  [0402]
J8  5103308-5  [HDR10X2-5103308_TYCO]
J9  TSM-102-01-T-SV  [CONN2-SMT-TSM-102-SV_SAMTEC]
J10  0532610671  [CONN6-53261_MOLEX]
R75  4.7k  [0402]
R76  10k  [0402]
R77  10k  [0402]
R78  10k  [0402]
R79  10k  [0402]
R80  DNI  [0402]
R81  10k  [0402]
R82  10k  [0402]
R83  4.7k  [0402]
R84  10k  [0402]
R85  DNI  [0402]
R86  DNI  [0402]
R87  DNI  [0402]
R88  DNI  [0402]
R89  4.7k  [0402]
R90  33  [0402]
SW1  TL1105F100Q  [SW4-TL1105_ESWITCH]
TP17  Testpoint  [TP-25RD12]
TP18  Testpoint  [TP-25RD12]
TP19  Testpoint  [TP-25RD12]
TP20  Testpoint  [TP-25RD12]
TP21  Testpoint  [TP-25RD12]
TP22  Testpoint  [TP-25RD12]
TP23  Testpoint  [TP-25RD12]
TP24  Testpoint  [TP-25RD12]
TP25  Testpoint  [TP-25RD12]
TP26  Testpoint  [TP-25RD12]
TP27  Testpoint  [TP-25RD12]
TP28  Testpoint  [TP-25RD12]
TP29  Testpoint  [TP-25RD12]
TP30  Testpoint  [TP-25RD12]
U17  SN74AHC1G125DBVR  [SOIC5-DBV_TI]
U18  TPS3838K33  [SOIC5-DBV_TI]
U19  SN74LVC1G07DBVR  [SOIC5-DBV_TI]
sheet P12-Controller I2C Trig GPIO
D5  LTST-C190EKT  [LED-LTST-C190_LITEON]
D6  LTST-C190GKT  [LED-LTST-C190_LITEON]
J11  TSM-102-01-T-SV  [CONN2-SMT-TSM-102-SV_SAMTEC]
J12  87832-1420  [CONN14-87832-1420_MOLEX]
J13  53261-0471  [CONN4-53261_MOLEX]
J14  53261-0471  [CONN4-53261_MOLEX]
J15  53261-0471  [CONN4-53261_MOLEX]
R91  1k  [0402]
R92  1k  [0402]
R93  1k  [0402]
R94  1k  [0402]
R95  1k  [0402]
R96  4.7k  [0402]
R97  120  [0402]
R98  0  [0402]
R99  0  [0402]
R100  10k  [0402]
R101  120  [0402]
R102  10k  [0402]
R103  10k  [0402]
R104  4.7k  [0402]
R105  10k  [0402]
R106  33  [0402]
R107  1k  [0402]
R108  1k  [0402]
R160  4.7k  [0402]
S_TP1  SMD_Testpoint  [TP-5015_KEY]
S_TP2  SMD_Testpoint  [TP-5015_KEY]
TP31  Testpoint  [TP-25RD12]
TP32  Testpoint  [TP-25RD12]
sheet P14-DMD Flex Connector
C160  4.7uF  [0603]
C161  0.1uF  [0402]
C162  0.1uF  [0402]
C163  0.1uF  [0402]
C164  0.1uF  [0402]
C165  4.7uF  [0603]
FB18  FBMH1608HM101-T  [0603]
FB19  FBMH1608HM101-T  [0603]
J16  DMD Flex Connector  [150PINS]
R111  DNI  [0402]
R112  DNI  [0402]
R113  1k  [0402]
R114  1k  [0402]
R115  DNI  [0402]
sheet P15-Power 1.15V, 1.8V, 3.3V
C166  0.1uF  [0402]
C167  0.1uF  [0402]
C168  100uF  [7343]
C169  100uF  [7343]
C170  100uF  [7343]
C171  0.1uF  [0402]
C172  0.1uF  [0402]
C173  10uF  [0805]
C174  68uF  [1206]
C175  68uF  [1206]
C176  10uF  [0805]
C177  68uF  [1206]
C178  10 nF  [0402]
C179  47nF  [0402]
C180  4.7uF  [0805]
C181  3900pF  [0603]
C182  100pF  [0402]
C183  4.7uF  [0805]
C184  82nF  [0603]
C185  56pF  [0402]
C186  0.1uF  [0402]
C187  47uF  [1210]
C188  22uF  [1206]
C189  47nF  [0402]
C190  4.7uF  [0805]
C191  0.033uF  [0402]
C192  120pF  [0402]
D7  SMCJ15CA  [DIO-DO214AB-A-SMC_COM-12]
D8  LTST-C190GKT  [LED-LTST-C190_LITEON]
F2  2410SFV10.0FM/125-2  [2410]
FB20  HI1206T500R-10  [1206]
J17  RAPC712X  [CONN3-RAPC712_SWITCHCRAFT]
J18  0039299062  [CONN6-5566_MOLEX]
L1  4.7uH  [IND2-XAL4030_COIL]
L2  4.7uH  [IND2-XAL4030_COIL]
L3  3.3uH  [IND2-XAL4030_COIL]
R116  1.5k  [0603]
R117  10k  [0402]
R118  10k  [0603]
R119  63.4k  [0402]
R120  88.7k  [0402]
R121  4.42k  [0603]
R122  12.7k  [0603]
R123  90.9k  [0402]
R124  4.02k  [0402]
R125  63.4k  [0402]
R126  2.21k  [0402]
R127  10k  [0402]
R128  10.5k  [0402]
R129  22.1k  [0402]
R130  10k  [0402]
R131  10k  [0402]
R132  63.4k  [0402]
R133  31.6k  [0402]
R134  63.4k  [0402]
R135  2.21k  [0402]
R136  10.5k  [0402]
R137  10k  [0402]
TP33  Testpoint  [TP-25RD12]
TP34  Testpoint  [TP-25RD12]
TP35  Testpoint  [TP-25RD12]
U20  TPS54320RHLR  [PQFP14-RHL_TI]
U21  TPS54320RHLR  [PQFP14-RHL_TI]
U22  TPS54620RGYR  [PQFP14-RGY_TI]
sheet P16-Power LDOs
C193  0.1uF  [0402]
C194  2.2uF  [0603]
C195  4.7uF  [0603]
C196  1.0uF  [0402]
C197  1.0uF  [0402]
GP1  Ground point  [TP-25RD12]
GP2  Ground point  [TP-25RD12]
GP3  Ground point  [TP-25RD12]
GP4  Ground point  [TP-25RD12]
GP5  Ground point  [TP-25RD12]
GP6  Ground point  [TP-25RD12]
GP7  Ground point  [TP-25RD12]
GP8  Ground point  [TP-25RD12]
GP9  Ground point  [TP-25RD12]
GP10  Ground point  [TP-25RD12]
GP11  Ground point  [TP-25RD12]
GP12  Ground point  [TP-25RD12]
GP13  Ground point  [TP-25RD12]
GP14  Ground point  [TP-25RD12]
GP15  Ground point  [TP-25RD12]
GP16  Ground point  [TP-25RD12]
R138  10k  [0603]
TP36  Testpoint  [TP-25RD12]
TP37  Testpoint  [TP-25RD12]
U23  TPS76618D  [SOIC8-D_TI]
U24  TLV117118DCY  [SOIC4-DCY_TI]
sheet P17-Inout Trigger, LED Driver
C198  0.1uF  [0402]
C199  0.1uF  [0402]
C200  0.1uF  [0402]
C201  0.1uF  [0402]
C202  0.1uF  [0402]
C203  0.1uF  [0402]
C204  0.1uF  [0402]
C205  0.1uF  [0402]
C206  0.1uF  [0402]
C207  0.1uF  [0402]
J19  TSM-103-01-T-SV  [CONN3-SMT-TSM-103-SV_SAMTEC]
J20  0532610671  [CONN6-53261_MOLEX]
J21  TSM-103-01-T-SV  [CONN3-SMT-TSM-103-SV_SAMTEC]
J22  TSM-103-01-T-SV  [CONN3-SMT-TSM-103-SV_SAMTEC]
J23  S14B-PHDSS(LF)(SN)(P)  [CONN14-S14B-PHDSS_JST]
J24  0532610671  [CONN6-53261_MOLEX]
J25  TSM-103-01-T-SV  [CONN3-SMT-TSM-103-SV_SAMTEC]
R139  10k  [0402]
R140  10k  [0402]
R141  10k  [0402]
R142  10k  [0402]
R143  10k  [0402]
R144  10k  [0402]
R145  10k  [0402]
R146  10k  [0402]
S_TP3  SMD_Testpoint  [TP-5015_KEY]
S_TP4  SMD_Testpoint  [TP-5015_KEY]
S_TP5  SMD_Testpoint  [TP-5015_KEY]
S_TP6  SMD_Testpoint  [TP-5015_KEY]
U25  SN74AVC1T45DRLR  [SOIC6-DRL_TI]
U26  SN74LVC1G17DBV  [SOIC5-DBV_TI]
U27  SN74AVC1T45DRLR  [SOIC6-DRL_TI]
U28  SN74LVC1G17DBV  [SOIC5-DBV_TI]
U29  SN74AVC1T45DRLR  [SOIC6-DRL_TI]
U30  SN74AVC1T45DRLR  [SOIC6-DRL_TI]
sheet P18-Gen pwrgood posense clk
C208  0.1uF  [0402]
C209  1.0uF  [0402]
C210  0.1uF  [0402]
D9  LTST-C190GKT  [LED-LTST-C190_LITEON]
Q1  FDV303N  [SOT23AVXE_GSD]
R147  4.7k  [0402]
R148  100  [0603]
R149  10k  [0402]
R150  1k  [0402]
R151  DNI  [0402]
R152  DNI  [0402]
R153  DNI  [0402]
R154  DNI  [0402]
R155  0  [0402]
R156  10k  [0402]
R157  0  [0402]
R158  0  [0402]
R159  0  [0402]
S_TP7  SMD_Testpoint  [TP-5015_KEY]
S_TP8  SMD_Testpoint  [TP-5015_KEY]
U31  TL7712ACDR  [SOIC8-D_TI]
U32  SN74LV21APWR  [SOIC14-PW_TI]
sheet P19-External Parallel Source
C211  22uF  [1206]
C212  1000pF  [0402]
C213  22uF  [1206]
C214  22uF  [1206]
J26  conn_120_QTH  [SAMTEC_QTH-060-01-X-D-A]
J27  TSM-103-01-T-SV  [SAMTEC_TSM-103-01-X-SV]
J28  TSM-103-01-T-SV  [SAMTEC_TSM-103-01-X-SV]
R161  0  [0402]
R162  0  [0402]
R163  0  [0402]
R164  0  [0402]
R165  0  [0402]
R166  10K  [0402]
R167  52.3K  [0402]
R168  10k  [0402]
R169  0  [0402]
R170  0  [0402]
R171  0  [0402]
R172  0  [0402]
U33  TPS82140  [MODULE_TPS82140]

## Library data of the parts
C78 C79 C84-C87 C161-C164 C210 C215-C217 = CER_0.1UF_16V_10%_X5R_0402: ALT_SYMBOLS: 0402-1MM
R67 R70-R73 R76-R82 R84-R88 R100 R102 R103 R105 R117 R131 R139-R146 R149 R151-R154 R156 R173-R177 = 10K_OHM_1_10W_5%_0402: ALT_SYMBOLS: 0402-1MM
R69 = 22_OHM_1_10W_1%_0402: ALT_SYMBOLS: 0402-1MM
U11 = DLPC900_910_datasheet
U34 = SN74ALVC08IDREP: MFG: TI
U35 = SN74LVC1G11DBVR: MFG: TI
U36 = S70GL02GS12FHIV20: MFG: TI
U37 = SN74AUP1G14DCKR: MFG: TI
J8 = CONN_HEADER_20POS_2.54mm
J9 J11 = TSM-102-01-T-SV_2POS_.1_SMD
J10 J20 J24 = CONN_HEADER_6POS_1.25MM_R_A_SMD
R75 R83 R89 R96 R104 R147 R160 = 4.7K_OHM_1_10W_5%_0402: ALT_SYMBOLS: 0402-1MM
R90 R106 = 33_OHM_1_16W_5%_0402: ALT_SYMBOLS: 0402-1MM
SW1 = SWITCH_TACTILE_SPST-NO
TP17-TP37 = Testpoint
U17 = 74AHC1G125
U18 = TPS3838K33
U19 = 74LVC1G07_IC_BUFF_NON-INVERT
D5 = LED_RED_CLEAR_0603
D6 D8 D9 = LED_GREEN_CLEAR_0603
J12 = 87832-1420_14POS_2ROWS_2MM_VERT
J13-J15 = TMP_090140
R91-R95 R107 R108 R111-R115 R150 = 1.0K_OHM_1_16W_5%_0402: ALT_SYMBOLS: 0402-1MM
R97 R101 = 120_OHM_1_10W_5%_0402: ALT_SYMBOLS: 0402-1MM
R98 R99 R155 R157-R159 R161-R165 R169-R172 = 0.0_OHM_1_10W_0402: ALT_SYMBOLS: 0402-1MM
S_TP1-S_TP8 = SMD_Testpoint
C160 C165 C195 = CER_4.7UF_16V_20%_X5R_0603
FB18 FB19 = FERRITE_BEAD_100_OHM_2A_0603
J16 = DMD_FLEX_CONNECTOR: MFG Part Number: Not-A-Part
C166 C167 = CER_0.1UF_50V_10%_X7R_0402: ALT_SYMBOLS: 0402-1MM
C168-C170 = TANT_100UF_25V_10%_2917
C171 C172 C186 C193 C198-C208 = CER_0.1UF_25V_10%_X5R_0402: ALT_SYMBOLS: 0402-1MM
C173 C176 = CER_10UF_25V_10%_X5R_0805
C174 C175 C177 = CER_68UF_10V_20%_X5R_1206
C178 = CER_10_nF_25V_10%_X5R_0402: ALT_SYMBOLS: 0402-1MM
C179 C189 = CER_0.047UF_16V_10%_X7R_0402: ALT_SYMBOLS: 0402-1MM
C180 C183 C190 = CER_4.7UF_50V_10%_X5R_0805
C181 = CER_3900PF_25V_5%_NP0_0603
C182 = CER_100PF_50V_5%_NPO_0402: ALT_SYMBOLS: 0402-1MM
C184 = CER_0.082UF_50V_10%_X7R_0603
C185 = CER_56PF_50V_5%_NPO_0402: ALT_SYMBOLS: 0402-1MM
C187 = CER_47UF_16V_20%_X5R_1210
C188 C211 C213 C214 = CER_22UF_25V_10%_X5R_1206
C191 = CER_0.033UF_16V_10%_X7R_0402: ALT_SYMBOLS: 0402-1MM
C192 = CER_120PF_50V_5%_NP0_0402: ALT_SYMBOLS: 0402-1MM
D7 = DIODE_TVS
F2 = FUSE_10A_125V_FAST_2410
FB20 = HI1206T500R-10_6A_50_OHM_1206
J17 = CON_PWRJACK3_RAPC712
J18 = PWR_CONN_HEADER_6POS_4.2MM_VERT
L1 L2 = INDUCTOR_4.7UH_4.5A_20%
L3 = INDUCTOR_3.3UH_5.5A_20%
R116 = 1.5K_OHM_1_10W_5%_0603
R118 R138 = 10K_OHM_1_10W_5%_0603
R119 R125 R132 R134 = 63.4K_OHM_1_10W_1%_0402: ALT_SYMBOLS: 0402-1MM
R120 = 88.7K_OHM_1_10W_1%_0402: ALT_SYMBOLS: 0402-1MM
R121 = 4.42K_OHM_1_10W_1%_0603
R122 = 12.7K_OHM_1_10W_.1%_0603
R123 = 90.9K_OHM_1_10W_1%_0402: ALT_SYMBOLS: 0402-1MM
R124 = 4.02K_OHM_1_16W_1%_0402: ALT_SYMBOLS: 0402-1MM
R126 R135 = 2.21K_OHM_1_10W_1%_0402: ALT_SYMBOLS: 0402-1MM
R127 R130 R137 R168 = 10K_OHM_1_16W_.1%_0402: ALT_SYMBOLS: 0402-1MM
R128 R136 = 10.5K_OHM_1_10W_1%_0402: ALT_SYMBOLS: 0402-1MM
R129 = 22.1K_OHM_1_10W_1%_0402: ALT_SYMBOLS: 0402-1MM
R133 = 31.6K_OHM_1_16W_.1%_0402: ALT_SYMBOLS: 0402-1MM
U20 U21 = TPS54320
U22 = TPS54620
C194 = CER_2.2UF_25V_10%_X5R_0603
C196 C197 C209 = CER_1.0UF_16V_10%_X5R_0402: ALT_SYMBOLS: 0402-1MM
GP1-GP16 = Ground_point
U23 = TPS76618_REG_LDO_1.8V_0.25A
U24 = TLV117118DCY_LDO_1.8V_1A_SOT223
J19 J21 J22 J25 = TSM-103-01-T-SV_3POS_.1_SMD
J23 = LED_CONN_HEADER_14POS_2MM
U25 U27 U29 U30 = SN74AVC1T45_level_translate
U26 U28 = SN74LVC1G17DBV_SCHMIT_TRIG
Q1 = FDV303N_MOSFET_N
R148 = 100_OHM_1_10W_5%_0603
U31 = TL7712A
U32 = SN74LV21A_DUAL_4-IN_AND_GATE
C212 = CER_1000PF_25V_10%_X7R_0402: ALT_SYMBOLS: 0402-1MM
J26 = conn_120_QTH: Connector, 120 pin; MFG: SAMTEC; MFG Part Number: QTH-060-01-L-D-A; Part Number: QTH-060-01-L-D-A; SOURCE: SAMTEC
J27 J28 = TSM-103-01-T-SV_3POS_.1_SMD: MFG Part Number: TSM-103-01-T-SV-TR
R166 R167 = 10K_OHM_1_10W_5%_0402
U33 = TPS82140SIL_TRANS_0: MFG Part Number: TPS82140SILR

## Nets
GND: C78.2 C79.2 C84.2 C85.2 C86.2 C87.2 C160.2 C161.2 C162.2 C163.2 C164.2 C165.2 C166.2 C167.2 C168.2 C169.2 C170.2 C173.2 C174.2 C175.2 C176.2 C177.2 C178.2 C179.2 C180.2 C181.2 C182.2 C183.2 C184.2 C185.2 C187.2 C188.2 C189.2 C190.2 C191.2 C192.2 C193.2 C194.2 C195.2 C196.2 C197.2 C198.2 C199.2 C200.2 C201.2 C202.2 C203.2 C204.2 C205.2 C206.2 C207.2 C208.2 C209.2 C210.2 C211.2 C212.2 C213.2 C214.2 C215.2 C216.2 C217.2 D5.1(CATHODE) D6.1(CATHODE) D7.2(ANODE) D8.1(CATHODE) GP1.1 GP2.1 GP3.1 GP4.1 GP5.1 GP6.1 GP7.1 GP8.1 GP9.1 GP10.1 GP11.1 GP12.1 GP13.1 GP14.1 GP15.1 GP16.1 J8.4 J8.6 J8.8 J8.10 J8.12 J8.14 J8.16 J8.18 J8.20 J9.2 J10.6 J10.7 J10.8 J11.2 J12.12 J12.13 J12.14 J13.4 J14.4 J15.4 J16.1A J16.1D J16.2C J16.2F J16.3A J16.3D J16.4C J16.4F J16.5A J16.5D J16.6C J16.6F J16.7A J16.7D J16.8C J16.8F J16.9A J16.9D J16.10C J16.10F J16.11A J16.11D J16.12C J16.12F J16.13D J16.14C J16.14F J16.15A J16.15D J16.16C J16.16F J16.17A J16.17D J16.18C J16.18F J16.19A J16.19D J16.20C J16.20F J16.21A J16.21D J16.22C J16.22F J16.23A J16.23D J16.24C J16.24F J16.25A J16.25D J17.2 J17.3 J18.1 J18.2 J18.3 J20.3 J20.6 J20.7 J20.8 J23.12(P12) J23.13(P13) J23.14(P14) J24.3 J24.6 J24.7 J24.8 J26.G1 J26.G2 J26.G3 J26.G4 J26.G5 J26.G6 J26.G7 J26.G8 Q1.S R81.2 R82.2 R89.2 R100.1 R102.2 R103.2 R105.2 R111.2 R115.2 R119.2 R120.2 R127.2 R128.2 R129.2 R130.2 R132.2 R136.2 R137.2 R140.2 R142.2 R144.2 R146.2 R149.2 R160.2 R162.1 R163.1 R164.2 R165.2 R166.2 R170.2 R171.2 R173.2 R174.2 R175.2 R176.2 R177.2 SW1.3 SW1.4 U11.AC6(VPGM) U11.M25(HW_TEST_EN) U17.2(A) U17.3(GND) U18.1(CT) U18.2(GND) U19.1(NC) U19.3(GND) U20.2(GND2) U20.3(GND3) U20.15(TPAD) U21.2(GND2) U21.3(GND3) U21.15(TPAD) U22.2(GND2) U22.3(GND3) U22.15(TPAD) U23.3(GND) U23.4(~{EN}) U24.2(GND) U24.4(TAB) U25.2(GND) U26.3(GND) U27.2(GND) U28.3(GND) U29.2(GND) U30.2(GND) U31.4(GND) U32.7(GND) U32.9(2A) U32.10(2B) U32.12(2C) U32.13(2D) U33.3(GND) U33.9(PAD) U34.7(GND) U35.2(GND) U36.E8(VSS) U36.H2(VSS_1) U36.H7(VSS_2) U37.3(GND) ; also on sheet 12 13 17 18 19 20
P5V: C213.1 C214.1 J26.9(A5) J26.11(A6) R167.1 R168.1 U33.4(VOUT_0) U33.5(VOUT_1)
P12V: C167.1 C168.1 C169.1 C170.1 C173.1 C176.1 C180.1 C183.1 C188.1 C190.1 C211.1 FB20.2 J16.15F J16.16A J16.16B J23.1(P1) J23.2(P2) J23.3(P3) R116.1 R123.1 R125.1 R134.1 R161.1 U20.4(PVIN4) U20.5(PVIN5) U20.6(VIN) U21.4(PVIN4) U21.5(PVIN5) U21.6(VIN) U22.4(PVIN4) U22.5(PVIN5) U22.6(VIN) U31.2(\\~{RESI}N) U31.7(SENSE) U31.8(VCC) U33.1(EN) U33.2(VIN)
P12V_CON: F2.1 J17.1 J18.4 J18.5 J18.6
P12V_F: C166.1 D7.1(CATHODE) F2.2 FB20.1
1P1V_SW_BOOT: C171.1 U20.13(BOOT)
1P1V_SW_COMP: C182.1 R124.1 U20.8(COMP)
1P1V_SW_EN: R123.2 R129.1 U20.10(EN)
1P1V_SW_PH: C171.2 L1.1 U20.11(PH11) U20.12(PH12)
1P1V_SW_PWRGD: R117.2 R155.1 U20.14(PWRGD)
1P1V_SW_RTCLK: R120.1 U20.1(RT/CLK)
1P1V_SW_SS: C178.1 U20.9(SS/TR)
1P1V_SW_VSENSE: R121.2 R127.1 U20.7(VSENSE)
1P8V_SW_BOOT: C172.1 U21.13(BOOT)
1P8V_SW_COMP: C185.1 R126.1 U21.8(COMP)
1P8V_SW_EN: R125.2 R128.1 U21.10(EN)
1P8V_SW_PH: C172.2 L2.1 U21.11(PH11) U21.12(PH12)
1P8V_SW_PWRGD: R118.2 R158.1 U21.14(PWRGD)
1P8V_SW_RTCLK: R119.1 U21.1(RT/CLK)
1P8V_SW_SS: C179.1 U21.9(SS/TR)
1P8V_SW_VSENSE: R122.2 R130.1 U21.7(VSENSE)
1P8VA_LDO_PG: R138.2 R157.1 U23.2(PG)
3P3V_SW_BOOT: C186.1 U22.13(BOOT)
3P3V_SW_COMP: C192.1 R135.1 U22.8(COMP)
3P3V_SW_EN: R134.2 R136.1 U22.10(EN)
3P3V_SW_PH: C186.2 L3.1 U22.11(PH11) U22.12(PH12)
3P3V_SW_PWRGD: R131.2 R159.1 U22.14(PWRGD)
3P3V_SW_RTCLK: R132.1 U22.1(RT/CLK)
3P3V_SW_SS: C189.1 U22.9(SS/TR)
3P3V_SW_VSENSE: R133.2 R137.1 U22.7(VSENSE)
AFE_ARSTZ: J26.108(B54) ; also on sheet 13 17
ALF_CSYNC: J26.49(A25) R162.2
ALF_HSYNC: J26.51(A26) R163.2
ALF_VSYNC: J26.50(B25) R164.1
BLU_LED_EN: J23.7(P7) R102.1 U11.D24(BLU_LED_EN)
BLU_LED_PWM: J23.10(P10) U11.C20(BLU_LED_PWM)
BT656_A_CLK: J26.94(B47) R171.1
BUS_SELECT: J26.89(A45) U11.H23(BUS_SELECT)
BUTTON_RSTZ: J9.1 R83.2 SW1.1 SW1.2 U18.3(\~{_M}R)
DADADDR0: J16.13E ; also on sheet 13
DADADDR1: J16.13F ; also on sheet 13
DADADDR2: J16.14A ; also on sheet 13
DADADDR3: J16.14B ; also on sheet 13
DADINTZ: J16.15E R113.2 ; also on sheet 13
DADMODE0: J16.15B ; also on sheet 13
DADMODE1: J16.15C ; also on sheet 13
DADOEZ: J16.12E R114.2 ; also on sheet 13
DADSEL0: J16.14D ; also on sheet 13
DADSEL1: J16.14E ; also on sheet 13
DADSTRB: J16.13C ; also on sheet 13
DASYNC: TP31.1 U11.R22(DA_SYNC_INPUT) U11.T23(FSD12_OUTPUT)
DMD_P3P3VA: C161.1 FB18.2 J16.1B J16.1C
DMD_P3P3VB: C163.1 FB19.1 J16.25E J16.25F
DMDSPARE0: J16.12D R111.1
DMDSPARE1: J16.11B R112.2 R115.1
EXT_CLK: J26.52(B26) R165.1
EXT_TRIG1_IN_VCC: C199.1 C200.1 J19.2 J20.1 R139.1 U25.1(Vcca) U26.5(VCC)
EXT_TRIG1_OUT_VCC: C205.1 J22.2 J24.1 U29.6(Vccb)
EXT_TRIG2_IN_VCC: C202.1 C203.1 J20.4 J21.2 R141.1 U27.1(Vcca) U28.5(VCC)
EXT_TRIG2_OUT_VCC: C207.1 J24.4 J25.2 U30.6(Vccb)
GPIO45_ADDR24: R177.1 U11.U23(GPIO_PM_ADDR24) U34.2(1B)
GPIO46_ADDR25: R176.1 U11.T22(GPIO_PM_ADDR25) U34.5(2B)
GPIO60_ADDR26: R175.1 U11.H22(GPIO_PM_ADDR26) U34.10(3B)
GRN_LED_EN: J23.6(P6) R103.1 U11.C25(GRN_LED_EN)
GRN_LED_PWM: J23.9(P9) U11.B20(GRN_LED_PWM)
HDMI_CEC: J26.13(A7) ; also on sheet 13
HDMI_INTZ: J26.91(A46) ; also on sheet 13 17
HOLDBOOTZ: J11.1 R95.1 U11.F24(HOLD_BOOTZ)
HRX_HPD: J26.90(B45) ; also on sheet 20
LED12VON: D8.2(ANODE) R116.2
M_DCLKA_N: J16.5C ; also on sheet 13
M_DCLKA_P: J16.5B ; also on sheet 13
M_DCLKB_N: J16.21C ; also on sheet 13
M_DCLKB_P: J16.21B ; also on sheet 13
M_DDA00_N: J16.10E ; also on sheet 13
M_DDA00_P: J16.10D ; also on sheet 13
M_DDA01_N: J16.9C ; also on sheet 13
M_DDA01_P: J16.9B ; also on sheet 13
M_DDA02_N: J16.9F ; also on sheet 13
M_DDA02_P: J16.9E ; also on sheet 13
M_DDA03_N: J16.8B ; also on sheet 13
M_DDA03_P: J16.8A ; also on sheet 13
M_DDA04_N: J16.8E ; also on sheet 13
M_DDA04_P: J16.8D ; also on sheet 13
M_DDA05_N: J16.7C ; also on sheet 13
M_DDA05_P: J16.7B ; also on sheet 13
M_DDA06_N: J16.7F ; also on sheet 13
M_DDA06_P: J16.7E ; also on sheet 13
M_DDA07_N: J16.6B ; also on sheet 13
M_DDA07_P: J16.6A ; also on sheet 13
M_DDA08_N: J16.5F ; also on sheet 13
M_DDA08_P: J16.5E ; also on sheet 13
M_DDA09_N: J16.4B ; also on sheet 13
M_DDA09_P: J16.4A ; also on sheet 13
M_DDA10_N: J16.4E ; also on sheet 13
M_DDA10_P: J16.4D ; also on sheet 13
M_DDA11_N: J16.3C ; also on sheet 13
M_DDA11_P: J16.3B ; also on sheet 13
M_DDA12_N: J16.3F ; also on sheet 13
M_DDA12_P: J16.3E ; also on sheet 13
M_DDA13_N: J16.2B ; also on sheet 13
M_DDA13_P: J16.2A ; also on sheet 13
M_DDA14_N: J16.2E ; also on sheet 13
M_DDA14_P: J16.2D ; also on sheet 13
M_DDA15_N: J16.1F ; also on sheet 13
M_DDA15_P: J16.1E ; also on sheet 13
M_DDB00_N: J16.16E ; also on sheet 13
M_DDB00_P: J16.16D ; also on sheet 13
M_DDB01_N: J16.17C ; also on sheet 13
M_DDB01_P: J16.17B ; also on sheet 13
M_DDB02_N: J16.17F ; also on sheet 13
M_DDB02_P: J16.17E ; also on sheet 13
M_DDB03_N: J16.18B ; also on sheet 13
M_DDB03_P: J16.18A ; also on sheet 13
M_DDB04_N: J16.18E ; also on sheet 13
M_DDB04_P: J16.18D ; also on sheet 13
M_DDB05_N: J16.19C ; also on sheet 13
M_DDB05_P: J16.19B ; also on sheet 13
M_DDB06_N: J16.19F ; also on sheet 13
M_DDB06_P: J16.19E ; also on sheet 13
M_DDB07_N: J16.20B ; also on sheet 13
M_DDB07_P: J16.20A ; also on sheet 13
M_DDB08_N: J16.21F ; also on sheet 13
M_DDB08_P: J16.21E ; also on sheet 13
M_DDB09_N: J16.22B ; also on sheet 13
M_DDB09_P: J16.22A ; also on sheet 13
M_DDB10_N: J16.22E ; also on sheet 13
M_DDB10_P: J16.22D ; also on sheet 13
M_DDB11_N: J16.23C ; also on sheet 13
M_DDB11_P: J16.23B ; also on sheet 13
M_DDB12_N: J16.23F ; also on sheet 13
M_DDB12_P: J16.23E ; also on sheet 13
M_DDB13_N: J16.24B ; also on sheet 13
M_DDB13_P: J16.24A ; also on sheet 13
M_DDB14_N: J16.24E ; also on sheet 13
M_DDB14_P: J16.24D ; also on sheet 13
M_DDB15_N: J16.25C ; also on sheet 13
M_DDB15_P: J16.25B ; also on sheet 13
M_EXT_RSTZ: J16.11F ; also on sheet 12
M_FIELD_GPIO78: J26.88(B44) ; also on sheet 13 17
M_FLASH0_WP#: R67.2 U36.B4(*WP)
M_GPIO8_PWM: J12.3 U11.A21(GPIO_PWM_0)
M_GPIO9_PWM: J12.5 U11.B21(GPIO_PWM_1)
M_GPIO10_PWM: J12.7 U11.A22(GPIO_PWM_2)
M_GPIO11_PWM: J12.9 U11.A23(GPIO_PWM_3)
M_GPIO23_AUX2: J12.11 U11.E21(GPIO_8)
M_GPIO43: J12.4 U11.U25(GPIO_4)
M_GPIO44: J12.6 U11.U24(GPIO_5)
M_GPIO49: J12.8 U11.V24(GPIO_6)
M_GPIO50: J12.10 U11.V23(GPIO_7)
M_GPIO66: R104.1 R106.1 U11.J23(TEST_FUNC_1)
M_IIC_BUSY: TP32.1 U11.G24(RESERVED)
M_P1A0: J26.85(A43) ; also on sheet 13 17
M_P1A1: J26.84(B42) ; also on sheet 13 17
M_P1A2: J26.83(A42) ; also on sheet 13 17
M_P1A3: J26.82(B41) ; also on sheet 13 17
M_P1A4: J26.81(A41) ; also on sheet 13 17
M_P1A5: J26.80(B40) ; also on sheet 13 17
M_P1A6: J26.79(A40) ; also on sheet 13 17
M_P1A7: J26.78(B39) ; also on sheet 13 17
M_P1A8: J26.77(A39) ; also on sheet 13 17
M_P1A9: J26.76(B38) ; also on sheet 13 17
M_P1B0: J26.75(A38) ; also on sheet 13 17
M_P1B1: J26.74(B37) ; also on sheet 13 17
M_P1B2: J26.73(A37) ; also on sheet 13 17
M_P1B3: J26.72(B36) ; also on sheet 13 17
M_P1B4: J26.71(A36) ; also on sheet 13 17
M_P1B5: J26.70(B35) ; also on sheet 13 17
M_P1B6: J26.69(A35) ; also on sheet 13 17
M_P1B7: J26.68(B34) ; also on sheet 13 17
M_P1B8: J26.67(A34) ; also on sheet 13 17
M_P1B9: J26.66(B33) ; also on sheet 13 17
M_P1C0: J26.65(A33) ; also on sheet 13 17
M_P1C1: J26.64(B32) ; also on sheet 13 17
M_P1C2: J26.63(A32) ; also on sheet 13 17
M_P1C3: J26.62(B31) ; also on sheet 13 17
M_P1C4: J26.61(A31) ; also on sheet 13 17
M_P1C5: J26.60(B30) ; also on sheet 13 17
M_P1C6: J26.59(A30) ; also on sheet 13 17
M_P1C7: J26.58(B29) ; also on sheet 13 17
M_P1C8: J26.57(A29) ; also on sheet 13 17
M_P1C9: J26.56(B28) ; also on sheet 13 17
M_P1DATEN: J26.87(A44) ; also on sheet 13 17
M_P1HS: J26.86(B43) ; also on sheet 13 17
M_P1VS: J26.55(A28) ; also on sheet 13 17
M_P2A0: J26.45(A23) ; also on sheet 13 17
M_P2A1: J26.44(B22) ; also on sheet 13 17
M_P2A2: J26.43(A22) ; also on sheet 13 17
M_P2A3: J26.42(B21) ; also on sheet 13 17
M_P2A4: J26.41(A21) ; also on sheet 13 17
M_P2A5: J26.40(B20) ; also on sheet 13 17
M_P2A6: J26.39(A20) ; also on sheet 13 17
M_P2A7: J26.38(B19) ; also on sheet 13 17
M_P2A8: J26.37(A19) ; also on sheet 13 17
M_P2A9: J26.36(B18) ; also on sheet 13 17
M_P2B0: J26.35(A18) ; also on sheet 13 17
M_P2B1: J26.34(B17) ; also on sheet 13 17
M_P2B2: J26.33(A17) ; also on sheet 13 17
M_P2B3: J26.32(B16) ; also on sheet 13 17
M_P2B4: J26.31(A16) ; also on sheet 13 17
M_P2B5: J26.30(B15) ; also on sheet 13 17
M_P2B6: J26.29(A15) ; also on sheet 13 17
M_P2B7: J26.28(B14) ; also on sheet 13 17
M_P2B8: J26.27(A14) ; also on sheet 13 17
M_P2B9: J26.26(B13) ; also on sheet 13 17
M_P2C0: J26.25(A13) ; also on sheet 13 17
M_P2C1: J26.24(B12) ; also on sheet 13 17
M_P2C2: J26.23(A12) ; also on sheet 13 17
M_P2C3: J26.22(B11) ; also on sheet 13 17
M_P2C4: J26.21(A11) ; also on sheet 13 17
M_P2C5: J26.20(B10) ; also on sheet 13 17
M_P2C6: J26.19(A10) ; also on sheet 13 17
M_P2C7: J26.18(B9) ; also on sheet 13 17
M_P2C8: J26.17(A9) ; also on sheet 13 17
M_P2C9: J26.16(B8) ; also on sheet 13 17
M_P2DATEN: J26.47(A24) ; also on sheet 13
M_P2HS: J26.46(B23) ; also on sheet 13
M_P2VS: J26.15(A8) ; also on sheet 13
M_PCLK1: J26.54(B27) ; also on sheet 13 17
M_PCLK2: J26.14(B7) ; also on sheet 13
M_PIPESTAT0: TP27.1 U11.C6(RESERVED)
M_PIPESTAT1: TP26.1 U11.B5(RESERVED)
M_PIPESTAT2: TP25.1 U11.A4(RESERVED)
M_PM_CEZ: U35.4(Y) U36.F2(*CE)
M_PM_CSZ0: R72.2 U11.D13(PM_CSZ_0) U35.1(A)
M_PM_CSZ1: R71.2 U11.E12(PM_CSZ_1) U34.1(1A) U34.4(2A) U34.9(3A) U35.3(B)
M_PM_CSZ2: R70.2 U11.A13(PM_CSZ_2) U35.6(C) U37.2(A)
M_PM_OEZ: U11.C13(PM_OEZ) U36.G2(*OE)
M_PM_WEZ: R69.1 U36.A5(*WE)
M_PMADDR00: U11.C7(PM_ADDR_00) U36.E2(A0)
M_PMADDR01: U11.A7(PM_ADDR_01) U36.D2(A1)
M_PMADDR02: U11.B7(PM_ADDR_02) U36.C2(A2)
M_PMADDR03: U11.C8(PM_ADDR_03) U36.A2(A3)
M_PMADDR04: U11.D8(PM_ADDR_04) U36.B2(A4)
M_PMADDR05: U11.A8(PM_ADDR_05) U36.D3(A5)
M_PMADDR06: U11.B8(PM_ADDR_06) U36.C3(A6)
M_PMADDR07: U11.C9(PM_ADDR_07) U36.A3(A7)
M_PMADDR08: U11.D9(PM_ADDR_08) U36.B6(A8)
M_PMADDR09: U11.E9(PM_ADDR_09) U36.A6(A9)
M_PMADDR10: U11.A9(PM_ADDR_10) U36.C6(A10)
M_PMADDR11: U11.B9(PM_ADDR_11) U36.D6(A11)
M_PMADDR12: U11.C10(PM_ADDR_12) U36.B7(A12)
M_PMADDR13: U11.D10(PM_ADDR_13) U36.A7(A13)
M_PMADDR14: U11.E10(PM_ADDR_14) U36.C7(A14)
M_PMADDR15: U11.C11(PM_ADDR_15) U36.D7(A15)
M_PMADDR16: U11.D11(PM_ADDR_16) U36.E7(A16)
M_PMADDR17: U11.A11(PM_ADDR_17) U36.B3(A17)
M_PMADDR18: U11.B11(PM_ADDR_18) U36.C4(A18)
M_PMADDR19: U11.C12(PM_ADDR_19) U36.D5(A19)
M_PMADDR20: U11.D12(PM_ADDR_20) U36.D4(A20)
M_PMADDR21: R173.1 U11.E11(PM_ADDR_21) U36.C5(A21)
M_PMADDR22: R174.1 U11.A12(PM_ADDR_22) U36.B8(A22)
M_PMADDR23: U36.C8(A23) U37.4(Y)
M_PMADDR24: U34.3(1Y) U36.F8(A24)
M_PMADDR25: U34.6(2Y) U36.G8(A25)
M_PMADDR26: U34.8(3Y) U36.B1(A26)
M_PMDATA_00: U11.B13(PM_DATA_00) U36.E3(DQ0)
M_PMDATA_01: U11.C14(PM_DATA_01) U36.H3(DQ1)
M_PMDATA_02: U11.D14(PM_DATA_02) U36.E4(DQ2)
M_PMDATA_03: U11.E13(PM_DATA_03) U36.H4(DQ3)
M_PMDATA_04: U11.A14(PM_DATA_04) U36.H5(DQ4)
M_PMDATA_05: U11.B14(PM_DATA_05) U36.E5(DQ5)
M_PMDATA_06: U11.C15(PM_DATA_06) U36.H6(DQ6)
M_PMDATA_07: U11.D15(PM_DATA_07) U36.E6(DQ7)
M_PMDATA_08: U11.E14(PM_DATA_08) U36.F3(DQ8)
M_PMDATA_09: U11.C16(PM_DATA_09) U36.G3(DQ9)
M_PMDATA_10: U11.D16(PM_DATA_10) U36.F4(DQ10)
M_PMDATA_11: U11.B15(PM_DATA_11) U36.G4(DQ11)
M_PMDATA_12: U11.A15(PM_DATA_12) U36.F5(DQ12)
M_PMDATA_13: U11.A16(PM_DATA_13) U36.G6(DQ13)
M_PMDATA_14: U11.B16(PM_DATA_14) U36.F6(DQ14)
M_PMDATA_15: U11.C17(PM_DATA_15) U36.G7(DQ15)
M_PMWEZ_PIN: R69.2 U11.B12(PM_WEZ)
M_POSENSE: R156.2 S_TP8.1 U32.6(1Y) U36.B5(*RESET) ; also on sheet 12
M_RTCK_PIN: R90.1 U11.E4(RTCK)
M_SCL0: J13.1 J27.1 R92.2 U11.A10(I2C0_SCL)
M_SCL1: J14.1 J26.95(A48) J27.3 R94.2 U11.D20(I2C1_SCL) ; also on sheet 17 20
M_SCL2: J15.1 R107.2 R169.1 U11.B22(I2C2_SCL)
M_SCTLA_N: J16.6E ; also on sheet 13
M_SCTLA_P: J16.6D ; also on sheet 13
M_SCTLB_N: J16.20E ; also on sheet 13
M_SCTLB_P: J16.20D ; also on sheet 13
M_SDA0: J13.2 J28.1 R91.2 U11.B10(I2C0_SDA)
M_SDA1: J14.2 J26.93(A47) J28.3 R93.2 U11.E19(I2C1_SDA) ; also on sheet 17 20
M_SDA2: J15.2 R108.2 R172.2 U11.C21(I2C2_SDA)
M_SEQ_AUX6: R98.1 U11.E26(SEQ_AUX6)
M_SEQ_AUX7: R99.1 U11.F26(SEQ_AUX7)
M_SEQ_INT1: R99.2 S_TP2.1 U11.G26(SEQ_INT1)
M_SEQ_INT2: R98.2 S_TP1.1 U11.H26(SEQ_INT2)
M_SEQSYNC_PIN: TP30.1 U11.AB9(SEQ_SYNC)
M_STATUS_GRN: R101.1 U11.AB12(HEARTBEAT)
M_STATUS_RED: R97.1 U11.AC11(FAULT_STATUS)
M_TRACECLK: TP29.1 U11.D7(RESERVED)
M_TRACESYNC: TP28.1 U11.A5(RESERVED)
M_TSTPT0: R88.2 TP24.1 U11.C2(RESERVED)
M_TSTPT1: R87.2 TP23.1 U11.D3(RESERVED)
M_TSTPT2: R86.2 TP22.1 U11.E6(RESERVED)
M_TSTPT3: R85.2 TP21.1 U11.D5(RESERVED)
M_TSTPT4: TP20.1 U11.E7(RESERVED)
M_TSTPT5: TP19.1 U11.C4(RESERVED)
M_TSTPT6: TP18.1 U11.B4(RESERVED)
M_TSTPT7: TP17.1 U11.E8(RESERVED)
M_USB_ENZ: U11.E25(USB_ENZ) ; also on sheet 12
MASTER_ASIC: R96.1 U11.V26(CTRL_MODE_CFG)
MFLASH_RYBYZ: R73.2 U36.A4(RY/*BY)
P1P8V: C177.1 J19.3 J21.3 J22.3 J25.3 L2.2 R122.1 TP34.1 ; also on sheet 18 19
P1P8V_A: C195.1 TP36.1 U23.7(OUT7) U23.8(OUT8) ; also on sheet 18
P1P8V_ITEA: C197.1 TP37.1 U24.3(VOUT) ; also on sheet 19
P1P15V: C174.1 C175.1 L1.2 R121.1 TP33.1 ; also on sheet 18
P3P3V: C78.1 C79.1 C84.1 C85.1 C86.1 C87.1 C160.1 C162.1 C164.1 C165.1 C187.1 C193.1 C194.1 C196.1 C198.1 C201.1 C204.1 C206.1 C210.1 C215.1 C216.1 C217.1 FB18.1 FB19.2 J8.1 J8.2 J12.1 J12.2 J13.3 J14.3 J15.3 J19.1 J21.1 J22.1 J23.11(P11) J25.1 L3.2 R67.1 R70.1 R71.1 R72.1 R73.1 R75.1 R76.1 R77.1 R78.1 R79.1 R80.1 R83.1 R84.1 R85.1 R86.1 R87.1 R88.1 R91.1 R92.1 R93.1 R94.1 R95.2 R96.2 R104.2 R107.1 R108.1 R112.1 R113.1 R114.1 R117.1 R118.1 R131.1 R133.1 R138.1 R143.1 R145.1 R147.1 R148.1 R151.1 R152.1 R153.1 R154.1 R156.1 TP35.1 U17.5(VCC) U18.5(VDD) U19.5(VCC) U23.5(IN5) U23.6(IN6) U24.1(VIN) U25.6(Vccb) U27.6(Vccb) U29.1(Vcca) U30.1(Vcca) U32.14(VCC) U34.14(VCC) U35.5(VCC) U36.D8(VIO) U36.F1(VIO_1) U36.G5(VCC) U37.5(VCC) ; also on sheet 12 13 17 18 19 20
PG12V_CT: C209.1 U31.3(CT)
PG12V_REF: C208.1 U31.1(REF)
PG12V_RST: R149.1 U31.6(RESET)
POS_1A_IN: R151.2 R157.2 U32.1(1A)
POS_1B_IN: R152.2 R155.2 U32.2(1B)
POS_1C_IN: R153.2 R158.2 U32.4(1C)
POS_1D_IN: R154.2 R159.2 U32.5(1D)
POWERGOOD: R147.2 R150.1 S_TP7.1 U19.4(Y) U31.5(\\~{RESE}T) ; also on sheet 12
RED_LED_EN: J23.5(P5) R100.2 U11.B26(RED_LED_EN)
RED_LED_PWM: J23.8(P8) U11.B19(RED_LED_PWM)
RTCK: J8.11 R78.2 R90.2
SCL: J26.115(A58) J27.2
SDA: J26.117(A59) J28.2
SLAVE_INT: R160.1 U11.V25(SLV_CTRL_PRST)
SRSTZ: J8.15 R84.2 U18.4(\~{_RESE}T) U19.2(A)
SSP0_CLK: J16.10B ; also on sheet 12
SSP0_CSZ0_DAD1: J16.12A ; also on sheet 12
SSP0_CSZ1_DMD: J16.11C ; also on sheet 12
SSP0_CSZ5_DAD2: J16.12B R106.2
SSP0_RXD_S2M: J16.11E ; also on sheet 12
SSP0_TXD_M2S: J16.10A ; also on sheet 12
TCK: J8.9 J10.5 R80.2 R82.1 U11.N24(TCK)
TDI: J8.5 J10.2 R76.2 U11.N25(TDI)
TDO1: J10.4 U11.N23(TDO1)
TDO2: J8.13 R79.2 U11.N22(TDO2)
TMS1: J10.3 U11.P25(TMS1)
TMS2: J8.7 R77.2 U11.P26(TMS2)
TRIG1_IN_CON: J20.2 U26.2
TRIG1_IN_T: U25.3(A) U26.4
TRIG1_OUT_CON: J24.2 U29.4(B)
TRIG2_IN_CON: J20.5 U28.2
TRIG2_IN_T: U27.3(A) U28.4
TRIG2_OUT_CON: J24.5 U30.4(B)
TRIGGER_IN1: R140.1 S_TP3.1 U25.4(B) ; also on sheet 12
TRIGGER_IN2: R142.1 S_TP4.1 U11.H25(TRIG_IN_2) U27.4(B)
TRIGGER_OUT_AUX0: R144.1 S_TP5.1 U11.E20(TRIG_OUT_1) U29.3(A)
TRIGGER_OUT_AUX1: R146.1 S_TP6.1 U11.D22(TRIG_OUT_2) U30.3(A)
TRSTZ: R75.2 U11.M23(TRSTZ) U17.4(Y)
TRSTZ_IN: J8.3 J10.1 R81.1 U17.1(~{OE})
UART1_RXD: J26.92(B46) R170.1
N20224398: R89.1 U11.M24(ICTSEN)
N20250700: R105.1 U11.AF8(RESERVED)
N20263361: D5.2(ANODE) R97.2
N20271735: D6.2(ANODE) R101.2
N20518299: R141.2 U27.5(DIR)
N20519329: R139.2 U25.5(DIR)
N20522932: R143.2 U29.5(DIR)
N20523509: R145.2 U30.5(DIR)
N20556337: C181.1 R124.2
N20557124: C184.1 R126.2
N21371449: D9.2(ANODE) R148.2
N21371451: Q1.G R150.2
N21371492: D9.1(CATHODE) Q1.D
N21714459: C191.1 R135.2
N22081511: J26.1(A1) R161.2
N22107027: C212.1 U33.8(SS_TR)
N22107424: R166.1 R167.2 U33.6(FB)
N22107486: R168.2 U33.7(PG)
N22130072: J26.113(A57) R169.2
N22134110: J26.114(B57) R172.1

Not connected (* = marked no-connect by the designer): J8 17* 19*; J13 5* 6*; J14 5* 6*; J15 5* 6*; J16 13A* 13B*; J23 4(P4); J26 2(B1)* 3(A2)* 4(B2)* 5(A3)* 6(B3)* 7(A4)* 8(B4)* 10(B5)* 12(B6)* 48(B24)* 53(A27)* 96(B48)* 97(A49)* 98(B49)* 99(A50)* 100(B50)* 101(A51)* 102(B51)* 103(A52)* 104(B52)* 105(A53)* 106(B53)* 107(A54)* 109(A55)* 110(B55)* 111(A56)* 112(B56)* 116(B58)* 118(B59)* 119(A60)* 120(B60)*; U11 A6(PM_BLSZ_0)* A19(RESERVED)* A20(RESERVED)* AB11(RESERVED)* AC9(RESERVED)* AC10(RESERVED)* AD10(RESERVED)* AE10(RESERVED)* AF10(RESERVED)* B6(PM_BLSZ_1)* B24(RESERVED)* C19(RESERVED)* C23(RESERVED)* C26(RESERVED)* D19(RESERVED)* D21(RESERVED)* E3(RESERVED)* E18(RESERVED)* E23(RESERVED)* G22(RESERVED)* G25(RESERVED)* H24(RESERVED)* J22(RESERVED)* J24(TEST_FUNC_2)* J25(TEST_FUNC_3)* J26(TEST_FUNC_4)* K22(TEST_FUNC_5)* K23(RESERVED)* K24(RESERVED)* U26(SSP0_CSZ4_SLV); U23 1(NC)*; U26 1; U28 1; U32 3(NC)* 8(2Y) 11(NC)*; U34 11(4Y)* 12(4A)* 13(4B)*; U36 A1(NC)* A8(NC_1)* C1(NC_2)* D1(NC_3)* E1(DNU)* F7(RFU)* G1(RFU_1)* H1(NC_4)* H8(NC_5)*; U37 1(NC)*

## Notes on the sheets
sheet 1
- REVISION HISTORY
- Rev A
- PAGES - ALL
- - initial rev
- Rev B
- PAGES for U11
- - Updated pins' name to match datasheet
- Rev C
- Remove all references to DLPC910
- Rev D
- PAGE 17
- - Removed reference to 5V
- PAGE 5
- - Updated U7
- Rev F
- Added External Parallel Video Connector and 5V rail
- PAGE 20
- - Added J26, J27, J28
- - Added R162, R163, R164, R165, R166, R167, R167, R168, R169, R170, R171, R172
- - Added R162, R163, R164, R165, R166, R167, R167, R168, R169, R170, R171, R172
- - Added U33
- - Added C211, C212, C213, C214
- PAGE 8
- - Added Net M_PCLK2 to U11A, W25
- - Added Net M_P2HS to U11A, W26
- - Added Net M_P2VS to U11A, U22
- - Added Net M_P2DATEN to U11A, W24
- - Added Net HDMI_CEC to U11A, G23
- PAGE 12
- - Added Net BUS_SELECT to U11I, W25
- Replaced External Flash Memory to 256 MByte
- PAGE 10
- - Removed U14, U15, U16
- - Removed C80, C81, C82, C83
- - Removed R68, R74
- - Added U34, U35, U36, U37
- - Added C215, C216, C217
- - Added Net GPIO45_ADDR24 to U11F, U23
- - Added Net GPIO46_ADDR25 to U11F, T22
- - Added Net GPIO60_ADDR26 to U11F, H22
- - Added Net M_PMADDR24 to U34, 3
- - Added Net M_PMADDR25 to U34, 6
- - Added Net M_PMADDR26 to U34, 8
- - Added Net M_PMADDR23 to U37, 4
- Rev G
- - Updated J10-1 pin net from TRSTZ to TRSTZ_IN
- - Update HDMI_HPD to HRX_HPD
- Rev H
- - Pull-Down resitors added to address lines 21-26 (R173, R174, R175, R176, R177)
  -Renamed Pin of U37 to "M_PM_CSZ2
  -U35 renamed Pin 4 to "M_PM_CEZ" and Pin 6 to "M_PM__CSZ2"
sheet 2
- Note:
  DO NOT INSTALL WITH
  HDMI/TFP503 ADC PCB
- Note:
  DO NOT INSTALL WITH
  HDMI/TFP503 ADC PCB
- 5V Supply for Ext ITE Front End
- Update part number
sheet 3
- IMPORTANT NOTICE FOR TI REFERENCE DESIGNS
- Texas Instruments Incorporated ("TI") reference designs are solely intended to assist designers (“Buyers”) who are developing systems that incorporate TI semiconductor products (also referred to herein
  as “components”). Buyer understands and agrees that Buyer remains responsible for using its independent analysis, evaluation and judgment in designing Buyer’s systems and products.
  TI reference designs have been created using standard laboratory conditions and engineering practices. TI has not conducted any testing other than that specifically described in the published documentation
  for a particular reference design. TI may make corrections, enhancements, improvements and other changes to its reference designs.
  Buyers are authorized to use TI reference designs with the TI component(s) identified in each particular reference design and to modify the reference design in the development of their end products.
  HOWEVER, NO OTHER LICENSE, EXPRESS OR IMPLIED, BY ESTOPPEL OR OTHERWISE TO ANY OTHER TI INTELLECTUAL PROPERTY RIGHT, AND NO LICENSE TO ANY
  THIRD PARTY TECHNOLOGY OR INTELLECTUAL PROPERTY RIGHT, IS GRANTED HEREIN, including but not limited to any patent right, copyright, mask work right, or other intellectual property
  right relating to any combination, machine, or process in which TI components or services are used. Information published by TI regarding third-party products or services does not constitute a license to
  use such products or services, or a warranty or endorsement thereof. Use of such information may require a license from a third party under the patents or other intellectual property of the third
  party, or a license from TI under the patents or other intellectual property of TI.
  TI REFERENCE DESIGNS ARE PROVIDED "AS IS". TI MAKES NO WARRANTIES OR REPRESENTATIONS WITH REGARD TO THE REFERENCE DESIGNS OR USE OF
  THE REFERENCE DESIGNS, EXPRESS, IMPLIED OR STATUTORY, INCLUDING ACCURACY OR COMPLETENESS. TI DISCLAIMS ANY WARRANTY OF TITLE AND
  ANY IMPLIED WARRANTIES OF MERCHANTABILITY, FITNESS FOR A PARTICULAR PURPOSE, QUIET ENJOYMENT, QUIET POSSESSION, AND NON-INFRINGEMENT
  OF ANY THIRD PARTY INTELLECTUAL PROPERTY RIGHTS WITH REGARD TO TI REFERENCE DESIGNS OR USE THEREOF. TI SHALL NOT BE LIABLE FOR AND SHALL
  NOT DEFEND OR INDEMNIFY BUYERS AGAINST ANY THIRD PARTY INFRINGEMENT CLAIM THAT RELATES TO OR IS BASED ON A COMBINATION OF COMPONENTS
  PROVIDED IN A TI REFERENCE DESIGN. IN NO EVENT SHALL TI BE LIABLE FOR ANY ACTUAL, SPECIAL, INCIDENTAL, CONSEQUENTIAL OR INDIRECT DAMAGES,
  HOWEVER CAUSED, ON ANY THEORY OF LIABILITY AND WHETHER OR NOT TI HAS BEEN ADVISED OF THE POSSIBILITY OF SUCH DAMAGES, ARISING IN ANY WAY
  OUT OF TI REFERENCE DESIGNS OR BUYER’S USE OF TI REFERENCE DESIGNS.
  TI reserves the right to make corrections, enhancements, improvements and other changes to its semiconductor products and services per JESD46, latest issue, and to discontinue any product or
  service per JESD48, latest issue. Buyers should obtain the latest relevant information before placing orders and should verify that such information is current and complete. All semiconductor products
  are sold subject to TI’s terms and conditions of sale supplied at the time of order acknowledgment.
  TI warrants performance of its components to the specifications applicable at the time of sale, in accordance with the warranty in TI’s terms and conditions of sale of semiconductor products.
  Testing and other quality control techniques for TI components are used to the extent TI deems necessary to support this warranty. Except where mandated by applicable law,
  testing of all parameters of each component is not necessarily performed.
  TI assumes no liability for applications assistance or the design of Buyers’ products. Buyers are responsible for their products and applications using TI components. To minimize the risks
  associated with Buyers’ products and applications, Buyers should provide adequate design and operating safeguards.
  Reproduction of significant portions of TI information in TI data books, data sheets or reference designs is permissible only if reproduction is without alteration and is accompanied by all associated
  warranties, conditions, limitations, and notices. TI is not responsible or liable for such altered documentation. Information of third parties may be subject to additional restrictions.
  Buyer acknowledges and agrees that it is solely responsible for compliance with all legal, regulatory and safety-related requirements concerning its products, and any use of TI components in its
  applications, notwithstanding any applications-related information or support that may be provided by TI. Buyer represents and agrees that it has all the necessary expertise to create
  and implement safeguards that anticipate dangerous failures, monitor failures and their consequences, lessen the likelihood of dangerous failures and take appropriate remedial actions.
  Buyer will fully indemnify TI and its representatives against any damages arising out of the use of any TI components in Buyer’s safety-critical applications.
  In some cases, TI components may be promoted specifically to facilitate safety-related applications. With such components, TI’s goal is to help enable customers to design and create their own
  end-product solutions that meet applicable functional safety standards and requirements. Nonetheless, such components are subject to these terms.
  No TI components are authorized for use in FDA Class III (or similar life-critical medical equipment) unless authorized officers of the parties have executed an agreement specifically governing such use.
  Only those TI components that TI has specifically designated as military grade or “enhanced plastic” are designed and intended for use in military/aerospace applications or environments. Buyer
  acknowledges and agrees that any military or aerospace use of TI components that have not been so designated is solely at Buyer's risk, and Buyer is solely responsible for compliance with all
  legal and regulatory requirements in connection with such use.
  TI has specifically designated certain components as meeting ISO/TS16949 requirements, mainly for automotive use. In any case of use of non-designated products, TI will not be responsible for any
  failure to meet ISO/TS16949.
sheet 4
- 3.3V to 1.8V @250mA LDO
  for controller 1.8V analog
- 3.3V to 1.8V @1A LDO
  for HDMI Rx 1.8V analog
- Distribute ground vias around PCB
- Power Generation LDO 1.8V LDOs
sheet 5
- 12V to 1.15V @2.5A
  Switching Freq ~ 550KHz
  Vstart/stop ~ 6.08V/5.57V
  SS ~ 3.5ms
- 12V to 1.8V @3A
  Switching Freq ~ 750KHz
  Vstart/stop ~ 8.44V/7.95V
  SS ~ 15ms
- 12V to 3.3V @5A
  Switching Freq ~ 750KHz
  Vstart/stop ~ 8.44V/7.95V
  SS ~ 15ms
- Power Generation 1.15V, 1.8V and 3.3V
sheet 6
- TI's EVM reference design has flex's
  electrical contact located  on the
  PCB's top (component) side
- DMD Flex
- DMD Flex Connector
sheet 7
- Use external voltage reference
  or on board 3.3V/1.8V supply.
  Do not use on board  3.3V or 1.8V as power source
  to external electronics.
- Input Trigger 1 to controller
- Input Trigger Port
- Input Trigger 2 to controller
- Use external voltage reference
  or on board 3.3V/1.8V supply.
  Do not use on board  3.3V or 1.8V as power source
  to external electronics.
- Output Trigger Port
- To LED driver board
- Input/Output Trigger and LED Driver Interface
sheet 8
- Per controller spec (Fig. 3), POWERGOOD has no
  impact on operation for 60ms after rising
  edge of POSENSE. In other words, during
  power up, controller will ignore the state of PG
  until the internal PLL is locked (require up to 60ms).
  Controller will then sample the PG input to begin
  normal operation.
  During power down, POSENSE has to remain
  valid high for at least 500us after PG is deasserted
  to allow controller to complete the DMD parking procedure.
  The 300+ uF input caps on 12V would ensure
  the power monitor to trip at ~11V to deassert PG
  while keeping regulators operational to maintain
  POSENSE for > 500us.
- D
- FDV303N
- G
- S
- Generate Powergood, POSENSE
sheet 9
- Install jumper to
  hold controller in
  boot mode
- Must have
  pullup on pin
  V26 and pulldown
  on pin V25 for
  normal
  operation
- GPIO User Connector
- Must connect pin
  E26 to H26, and
  pin F26 to G26
  for normal
  operation
- I2C Port 0
- I2C Port 1
- I2C Port 2
- Controller I2C, LED driver interface, In/Out Triggers and GPIOs
sheet 10
- ARM Multi-ICE debug port
- Install jumper to hold controllers in reset
- Pullup on open-drain signal
  POWERGOOD found on page 18
- JTAG Boundary scan port may be
  used to download flash image using
  USB-to-JTAG FTDI adapter board
- Controller Multi-ICE Port
sheet 11
- Tied open drain outputs together
- Refer to the DLPC900 datasheet
  for other memory configurations.
- It is recommended that pin 53 of M29DW128G70NF6E is tied
- to 3.3V with a 10k resistor to enable compatibility with
- 1
- future flash devices.
- Controller Flash Interface
- 1
